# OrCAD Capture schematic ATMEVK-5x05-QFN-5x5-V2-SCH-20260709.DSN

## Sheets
1 01. TITLE: title: ATM5305/5205 5x5 QFN EVALUATION BOARD; rev: 2; note: 108-20-210-xxxx
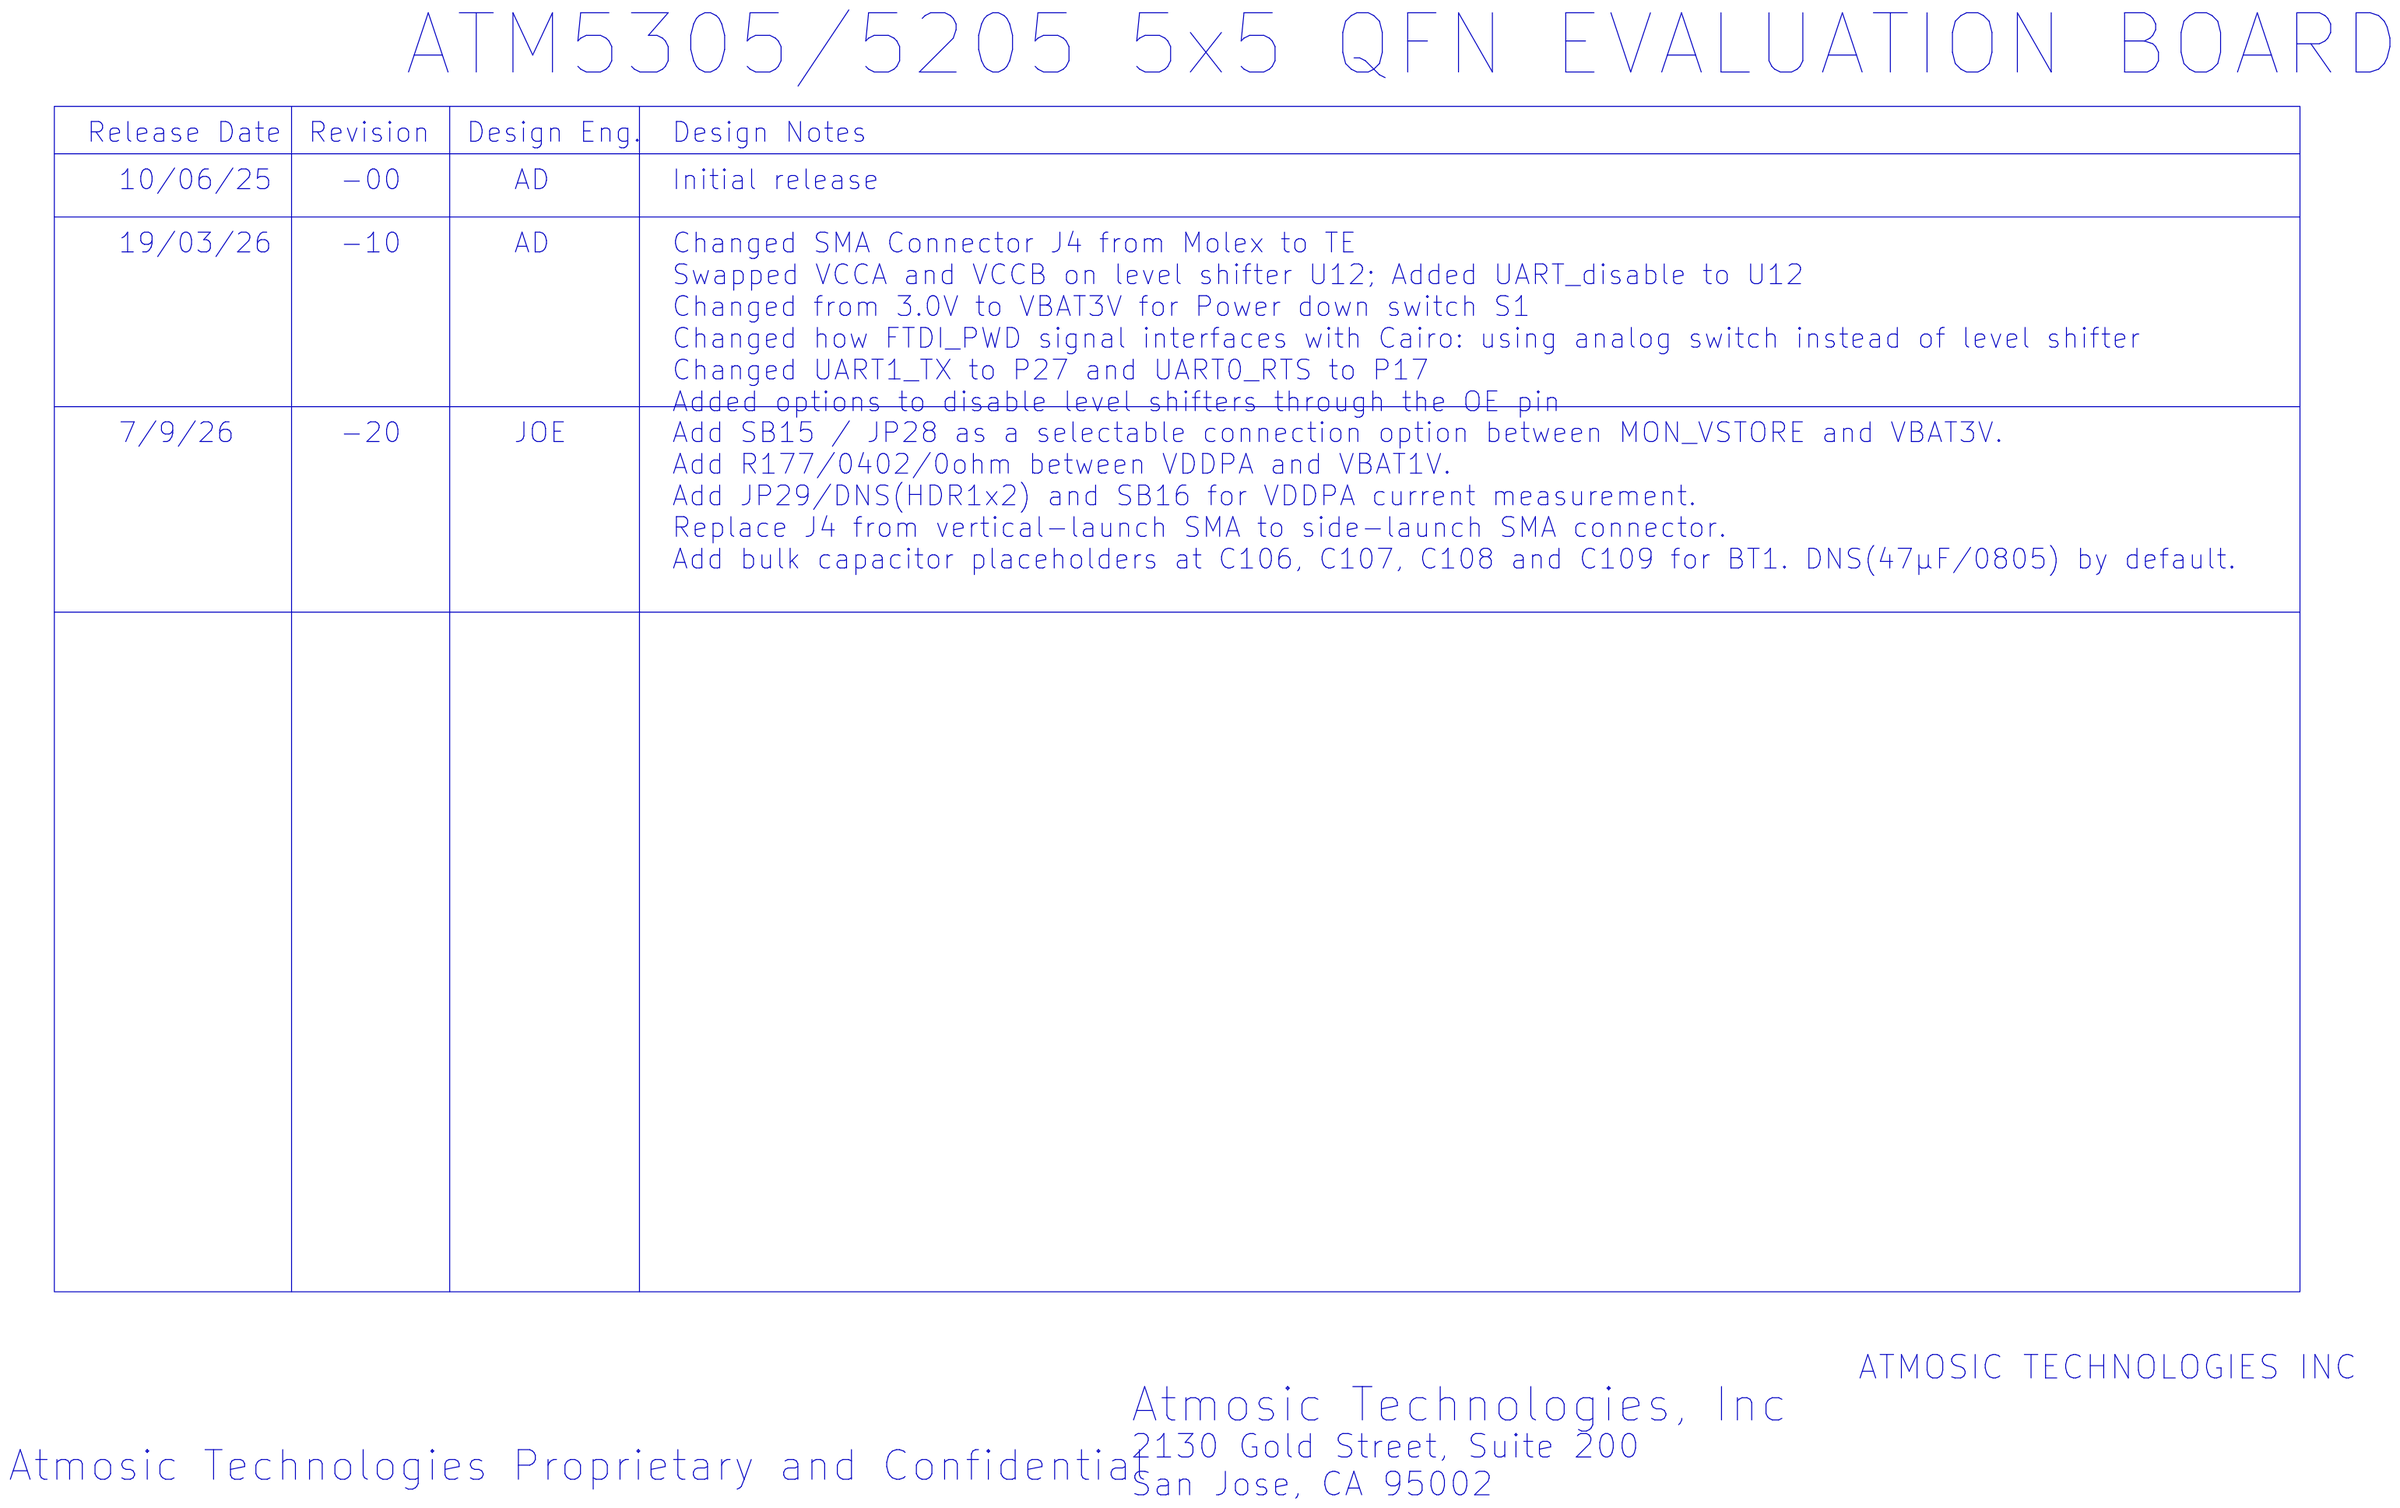
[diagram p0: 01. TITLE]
2 02. Block Diagram: title: ATM5305 QFN 5x5 EVALUATION BOARD
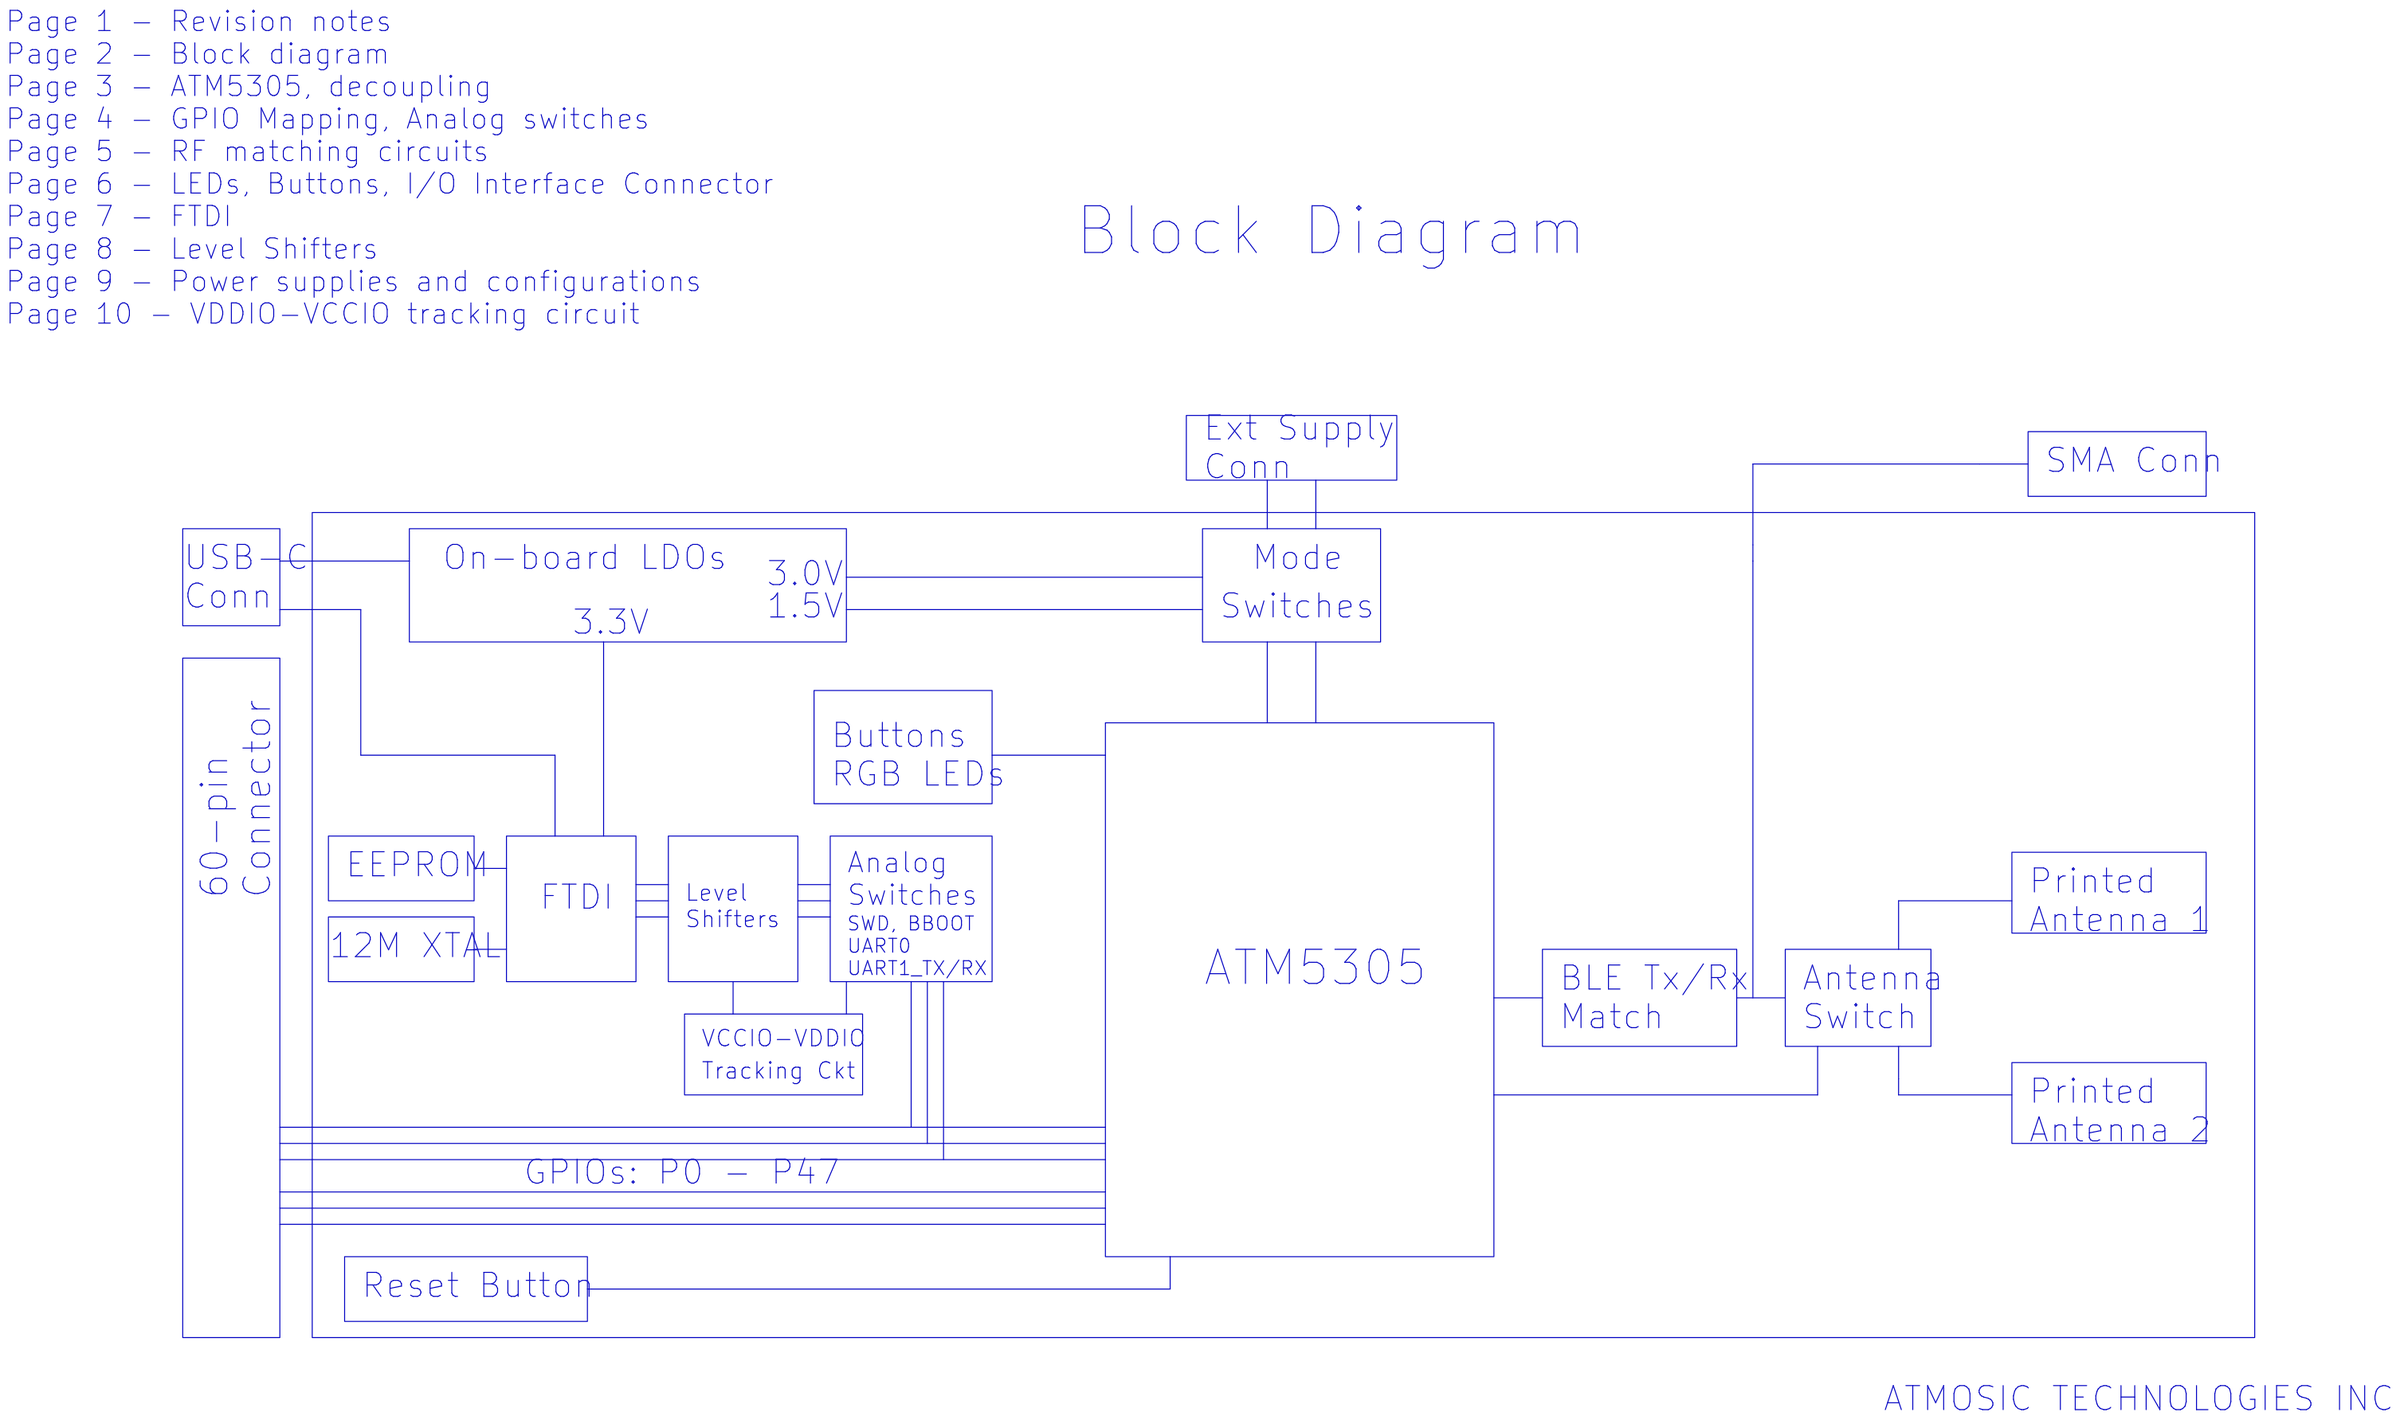
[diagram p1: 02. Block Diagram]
3 03. ATM5305-2NC8QK: size B; title: ATM5305 QFN 5x5 EVALUATION BOARD
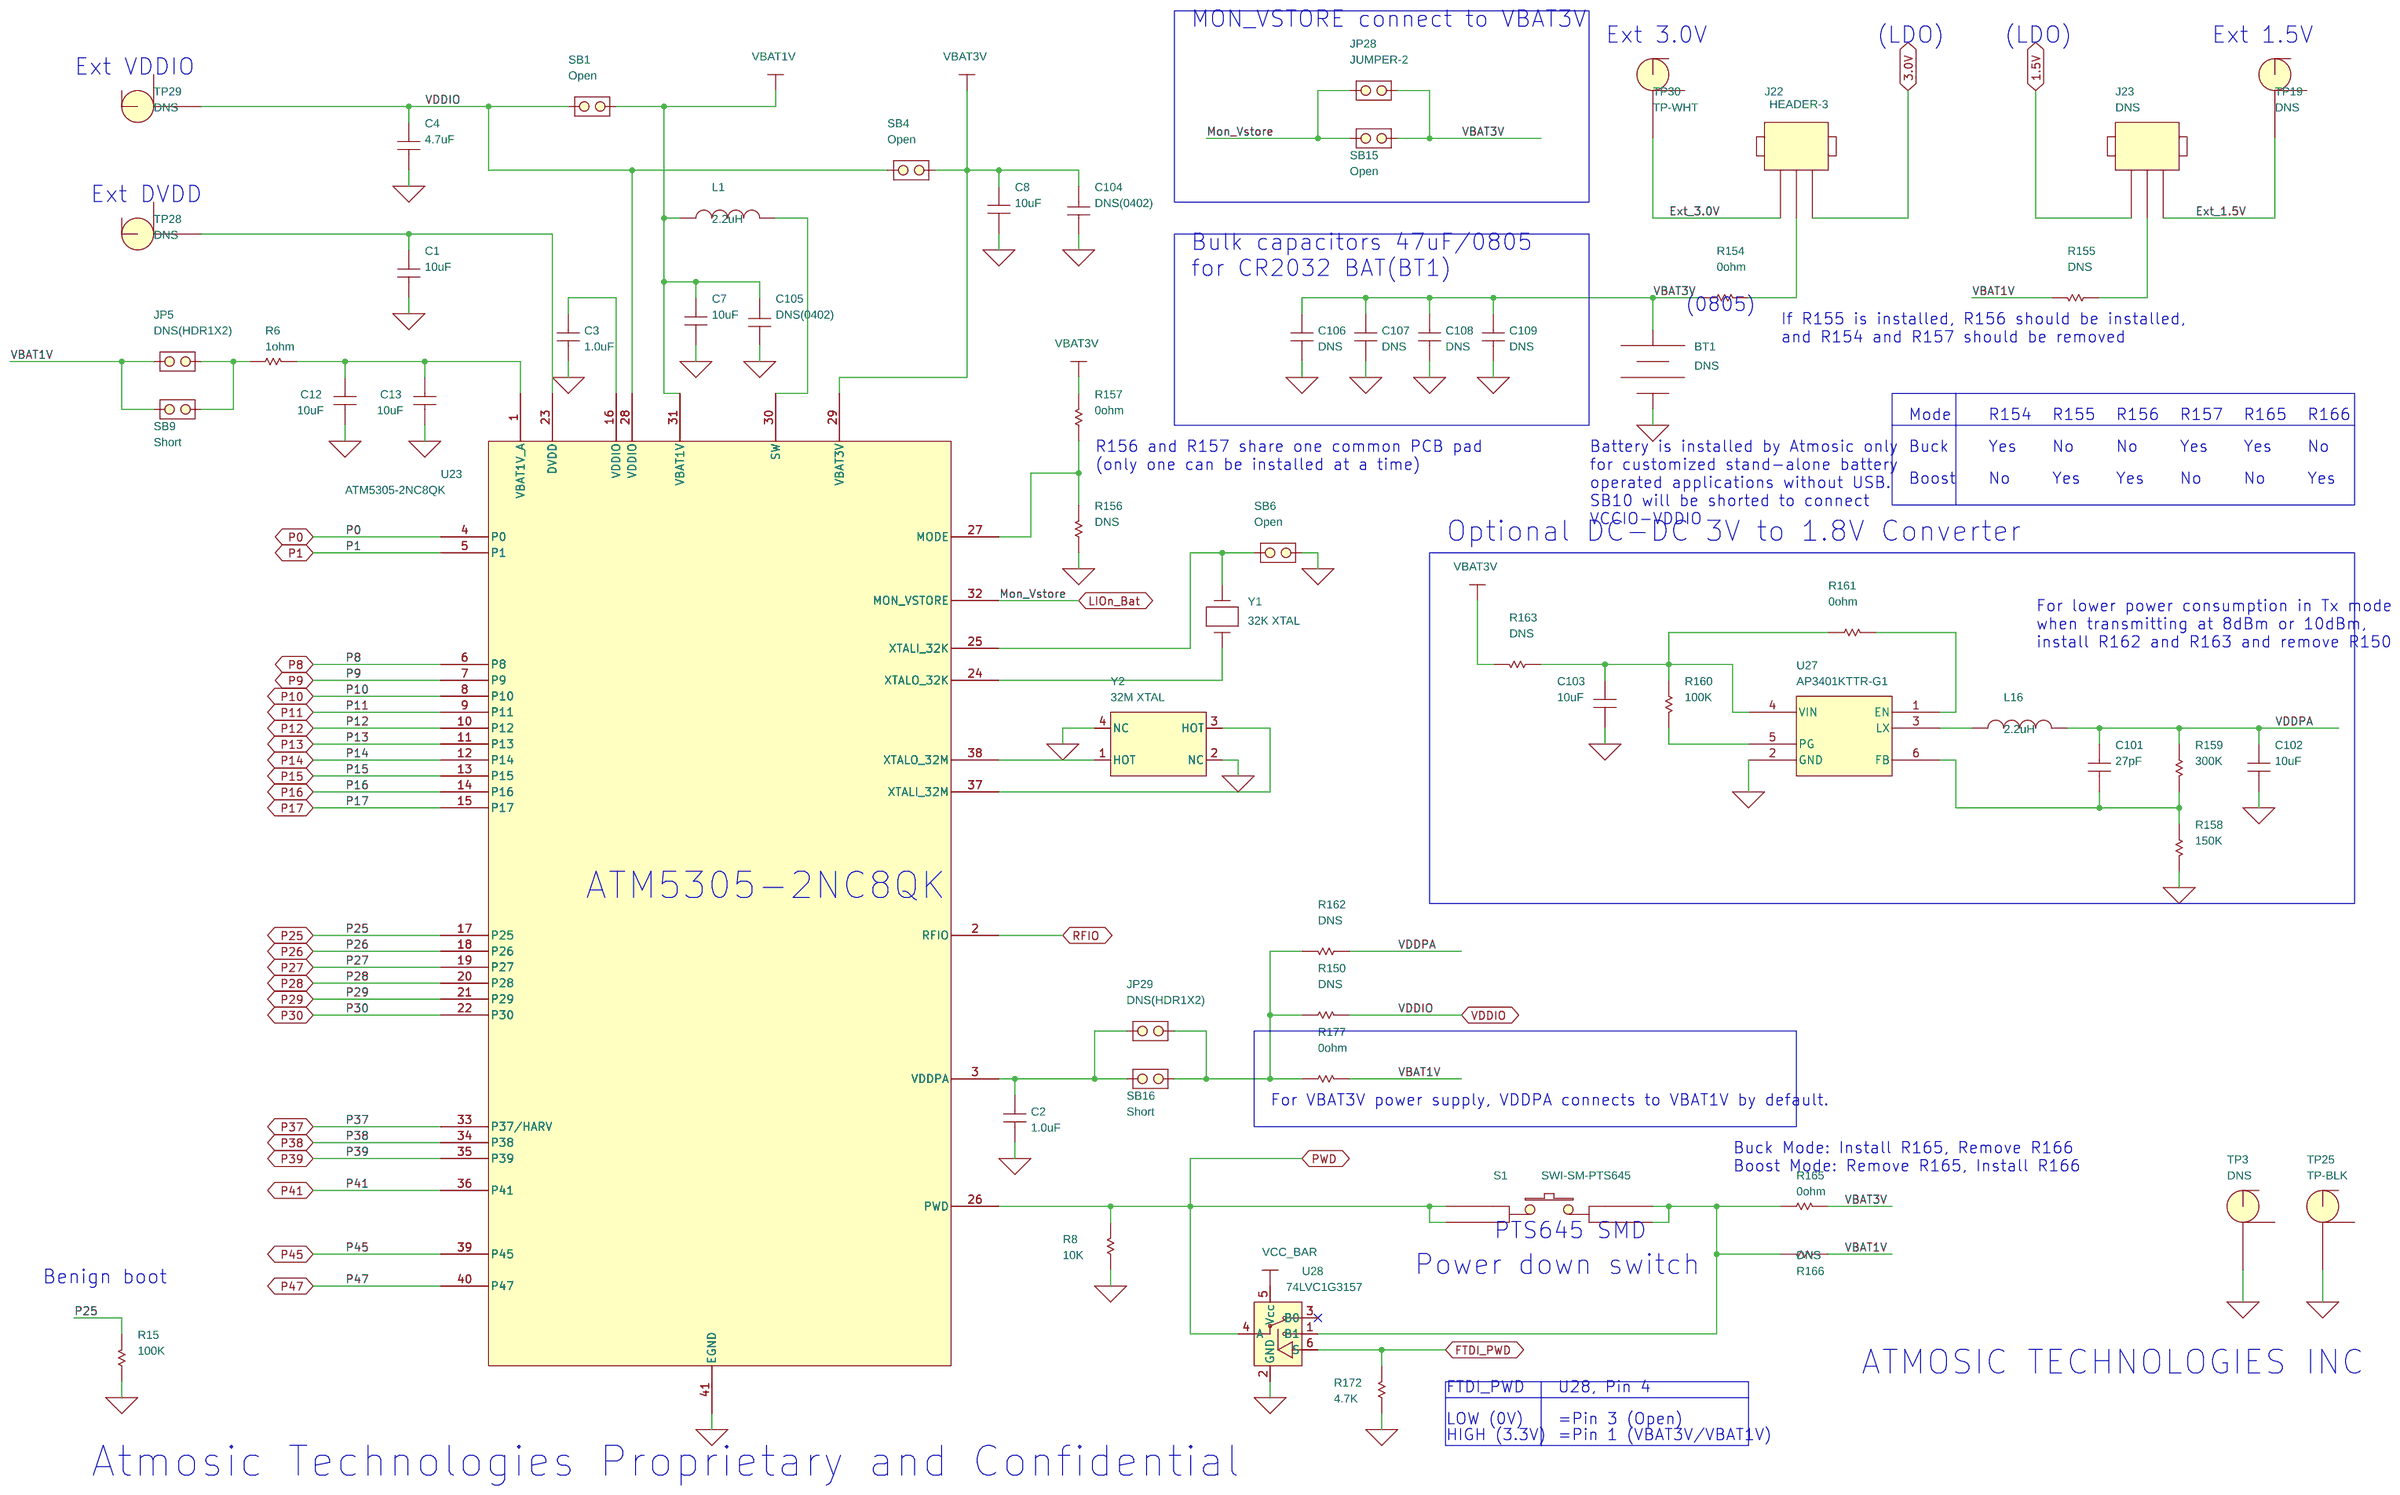
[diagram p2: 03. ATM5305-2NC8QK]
4 04. GPIO Mapping: size B; title: ATM5305 QFN 5x5 EVALUATION BOARD
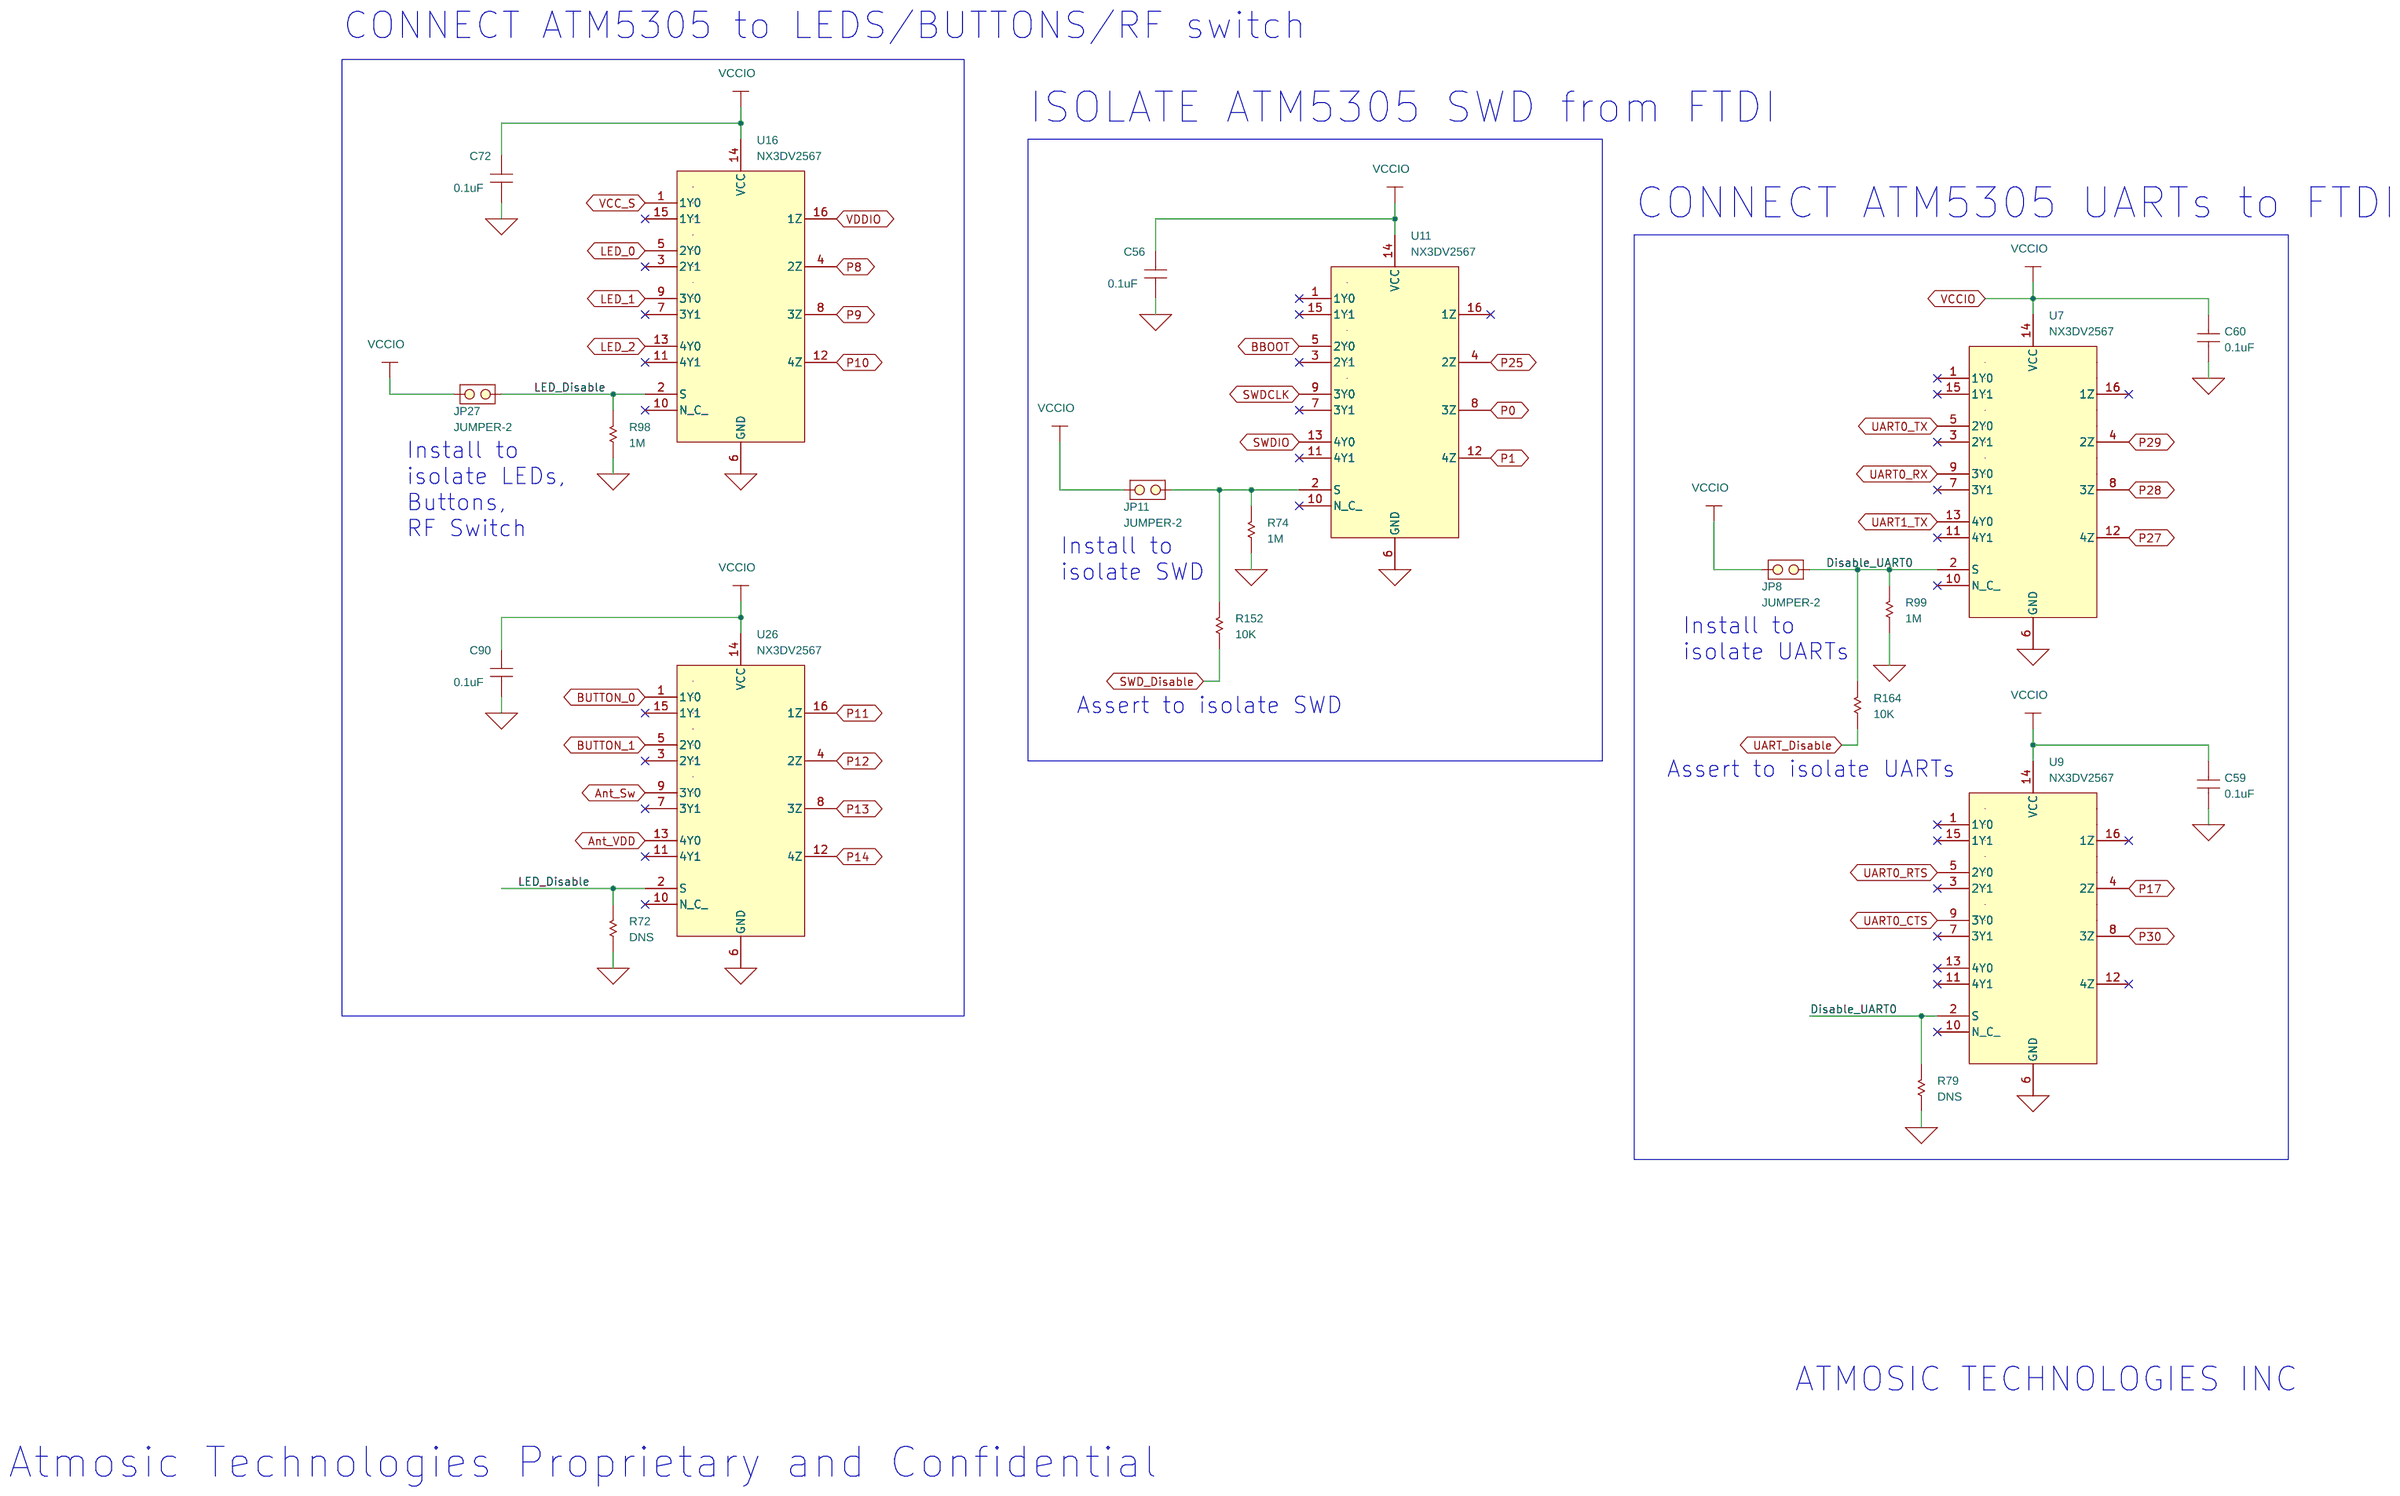
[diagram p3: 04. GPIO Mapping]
5 07. FTDI and USB: size B; title: ATM5305 QFN 5x5 EVALUATION BOARD
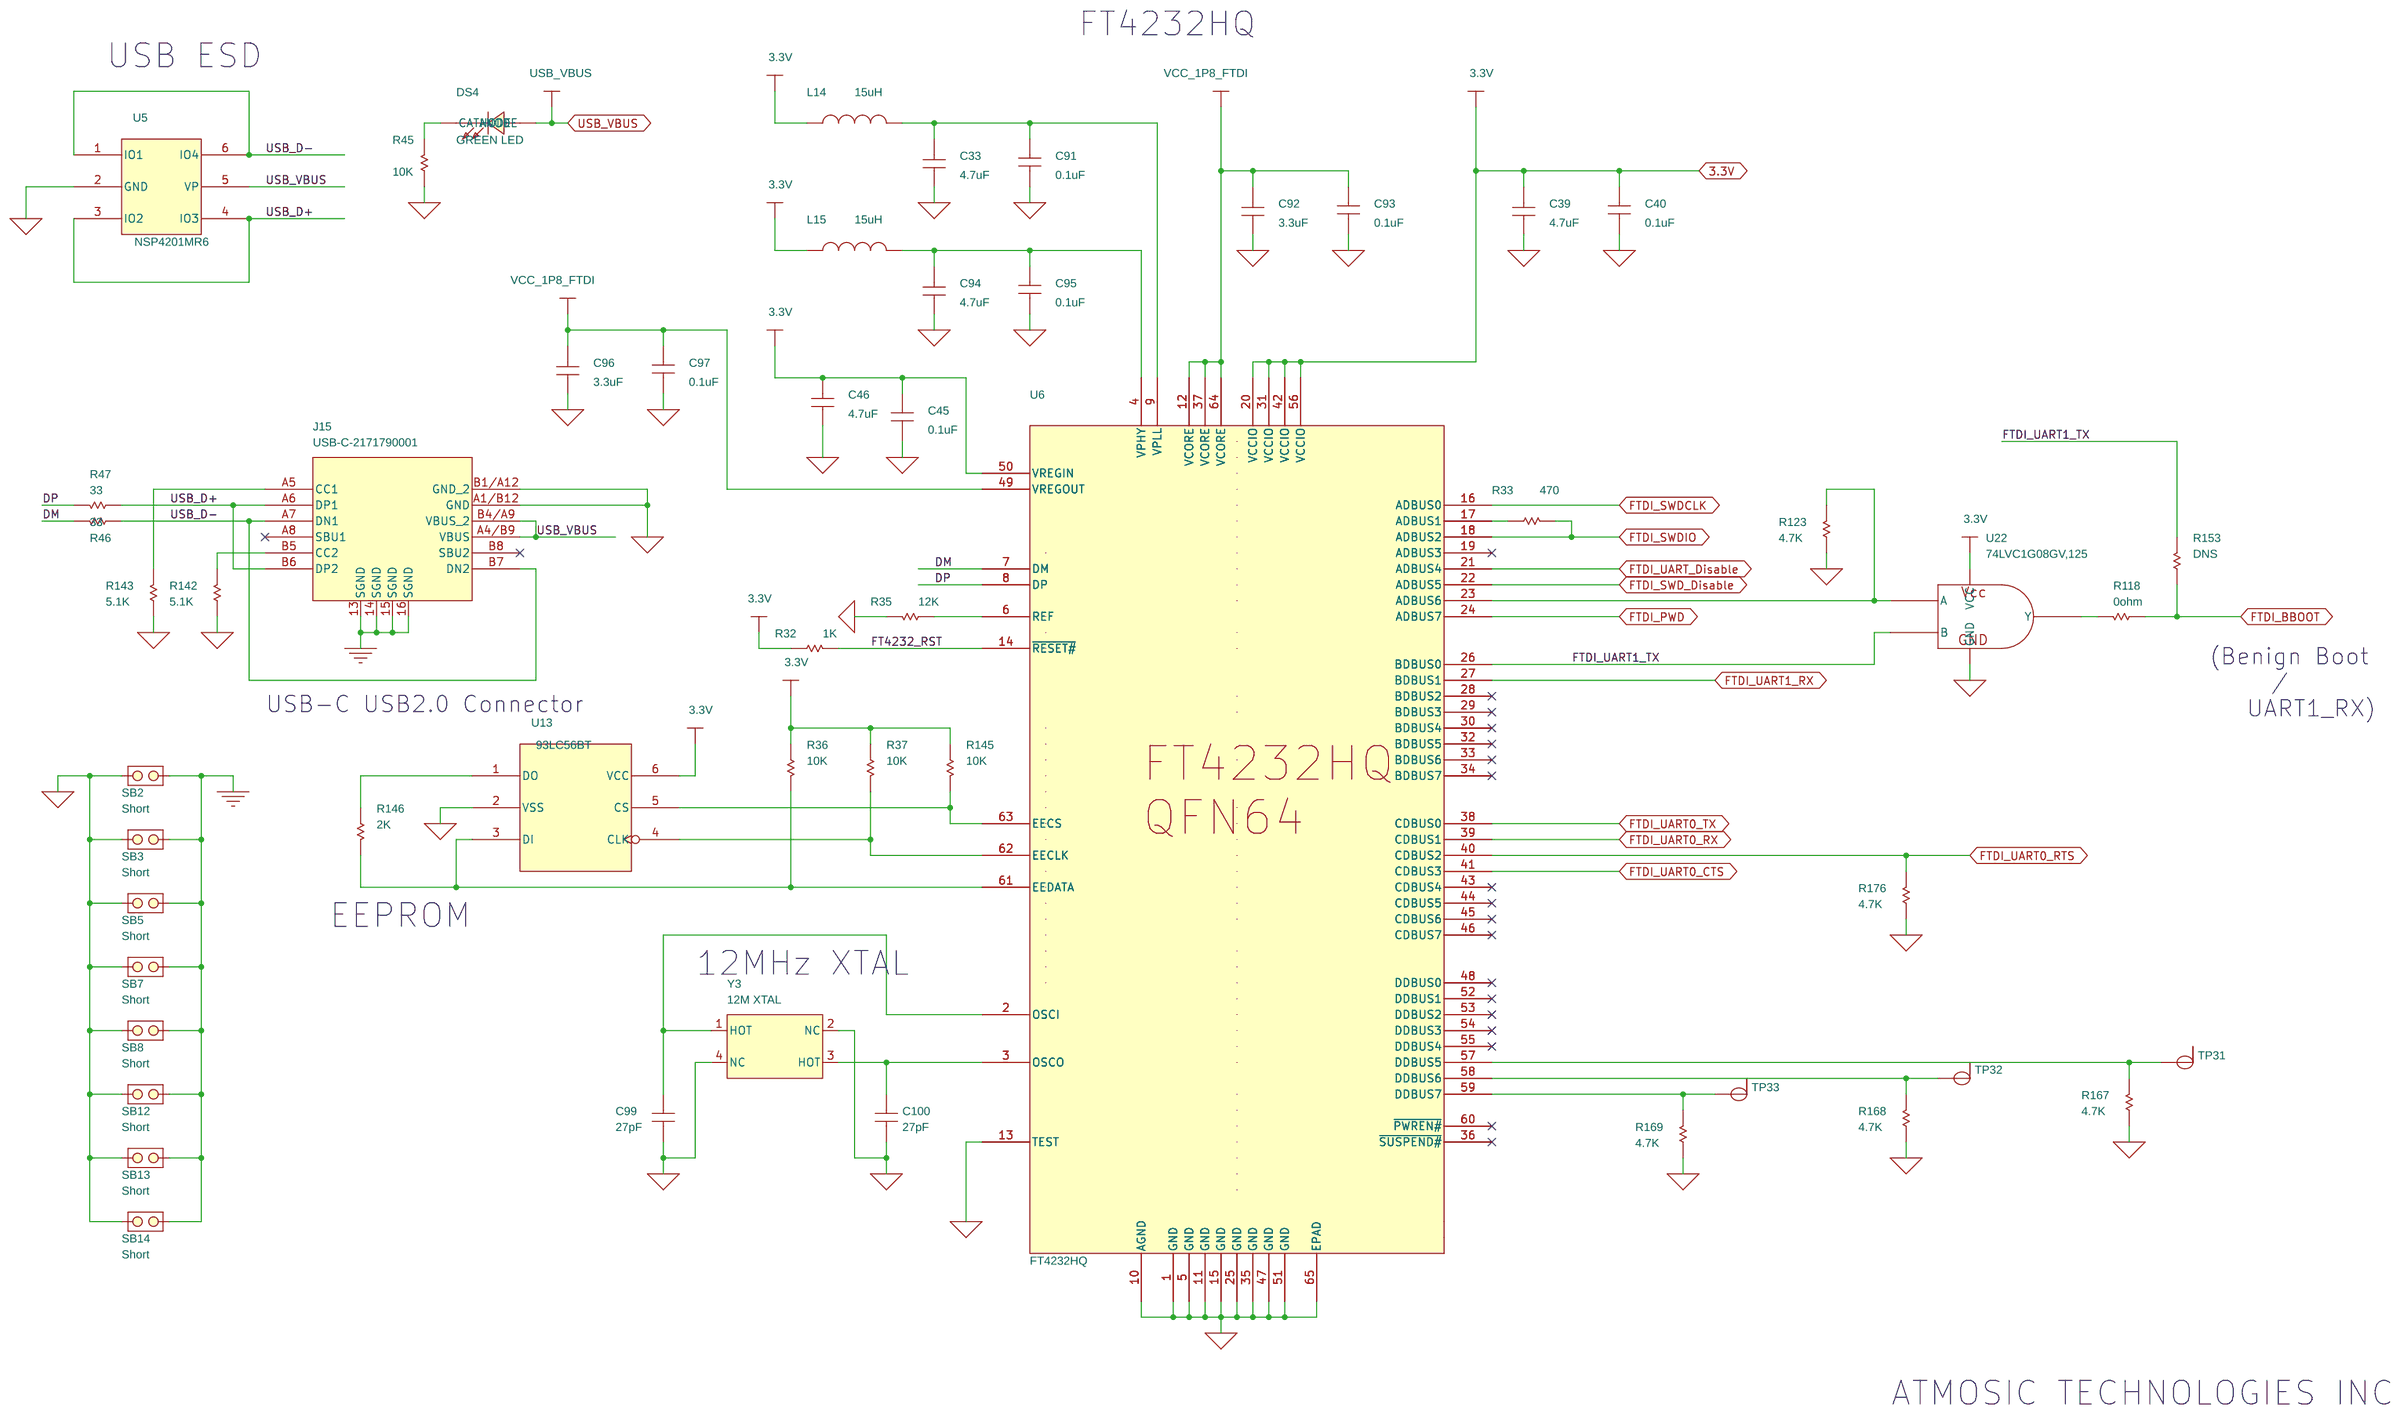
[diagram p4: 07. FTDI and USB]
6 08. Level Shifters: size B; title: ATM5305 QFN 5x5 EVALUATION BOARD
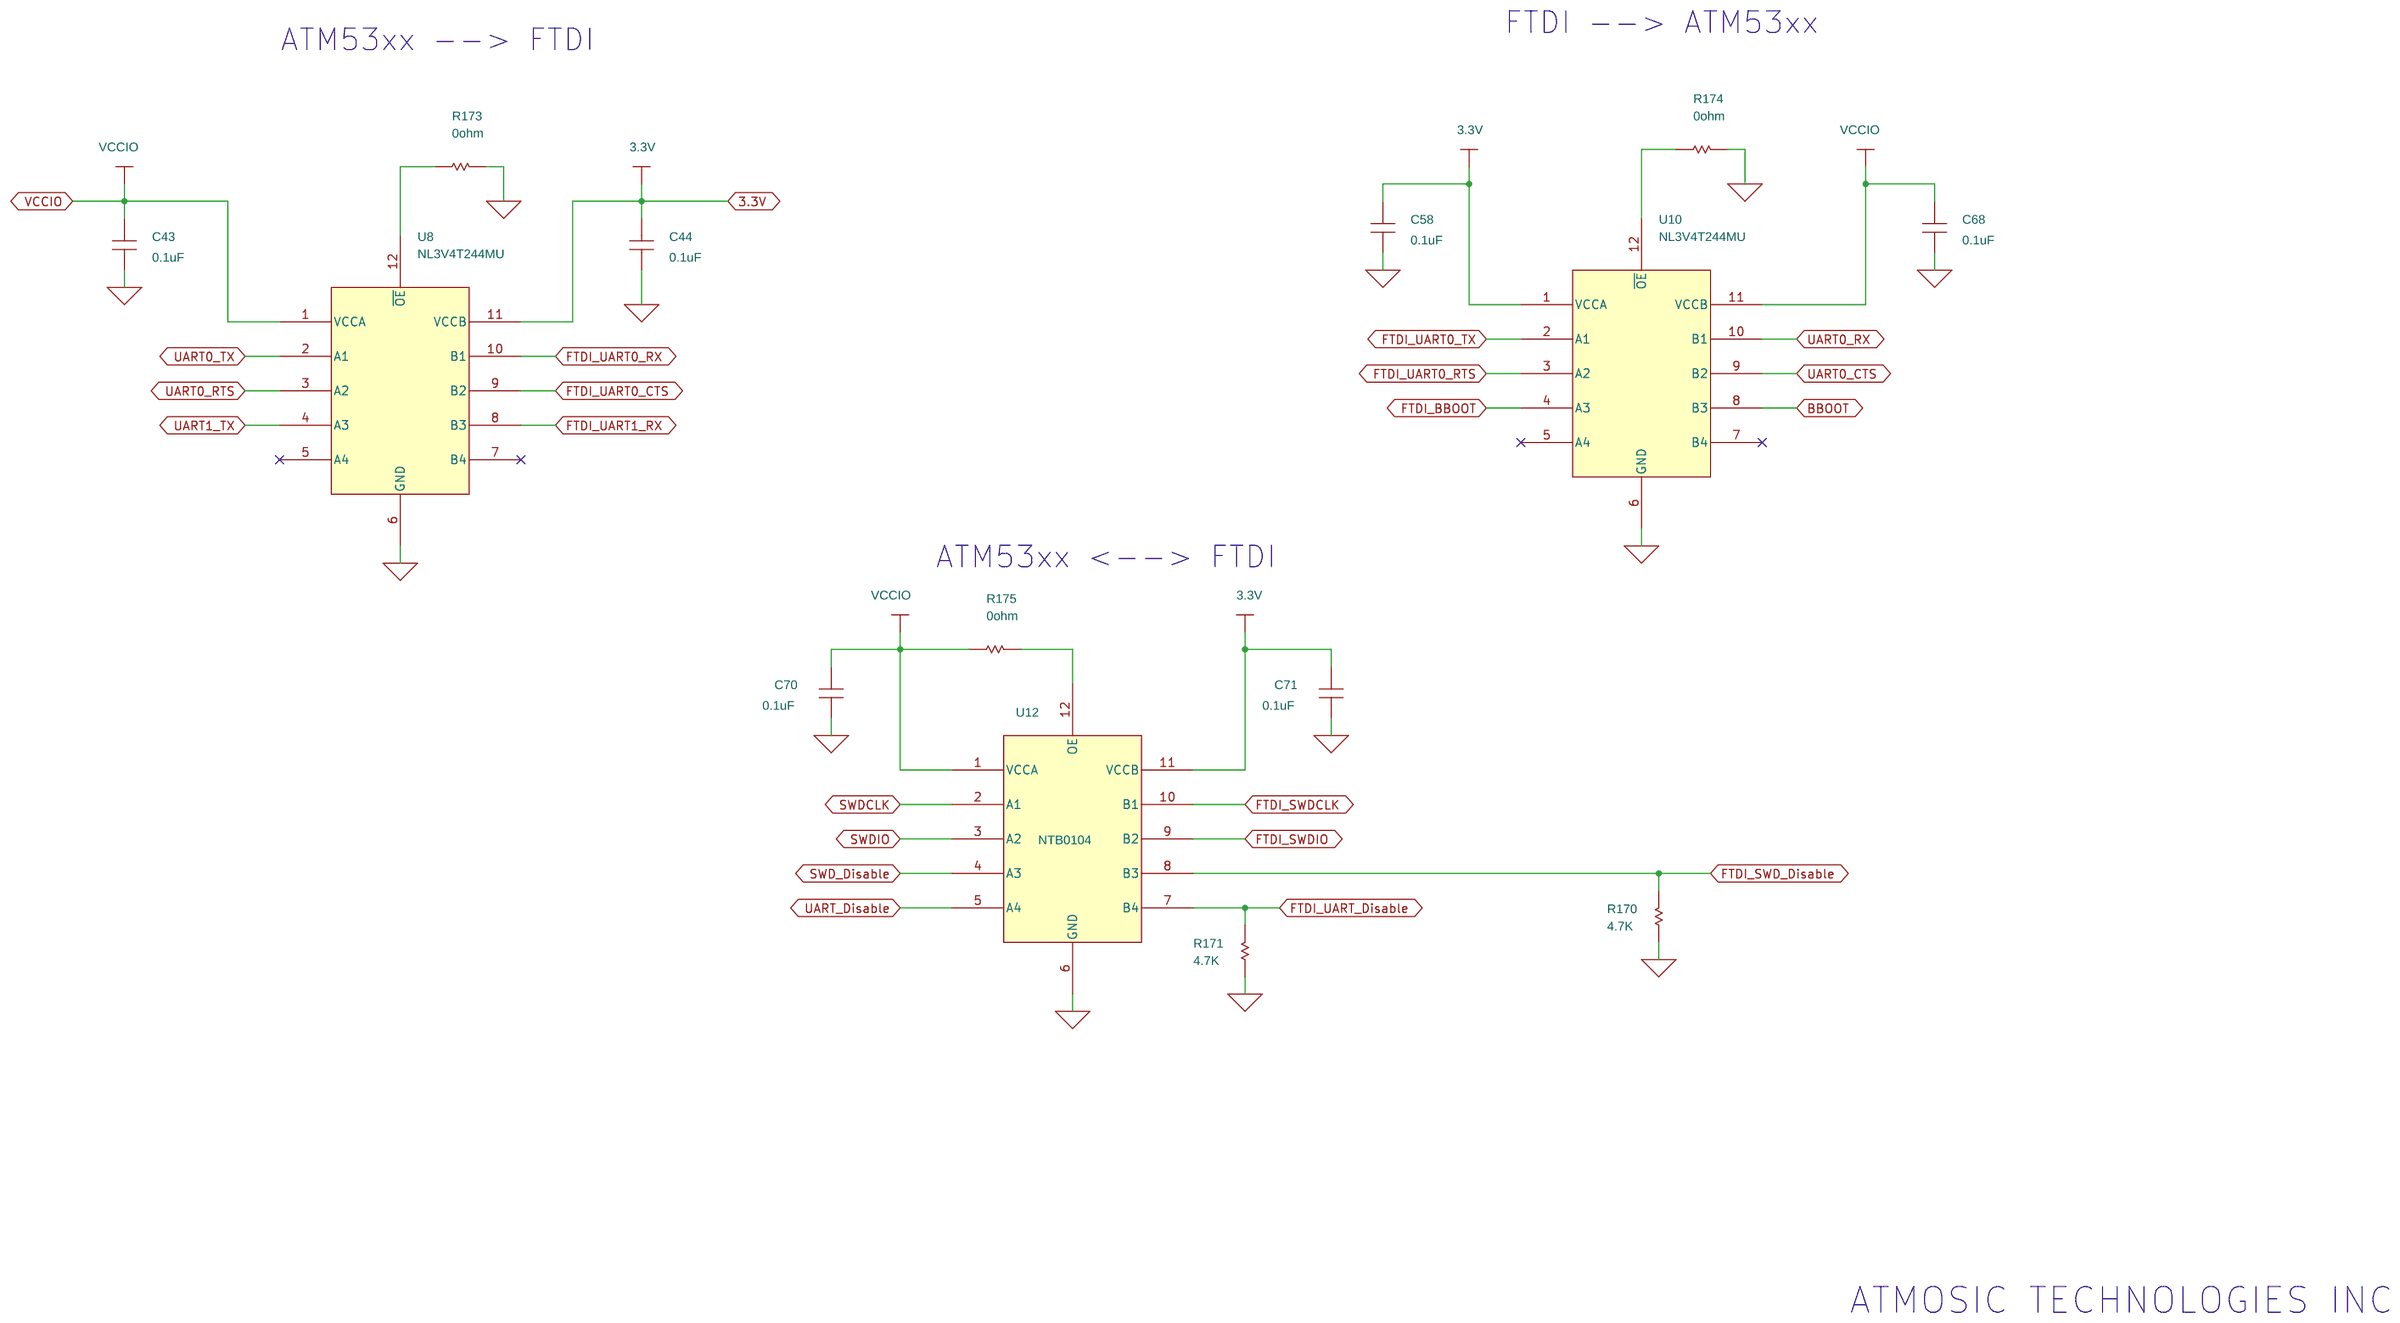
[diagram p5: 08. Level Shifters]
7 09. Power: size B; title: ATM5305 QFN 5x5 EVALUATION BOARD
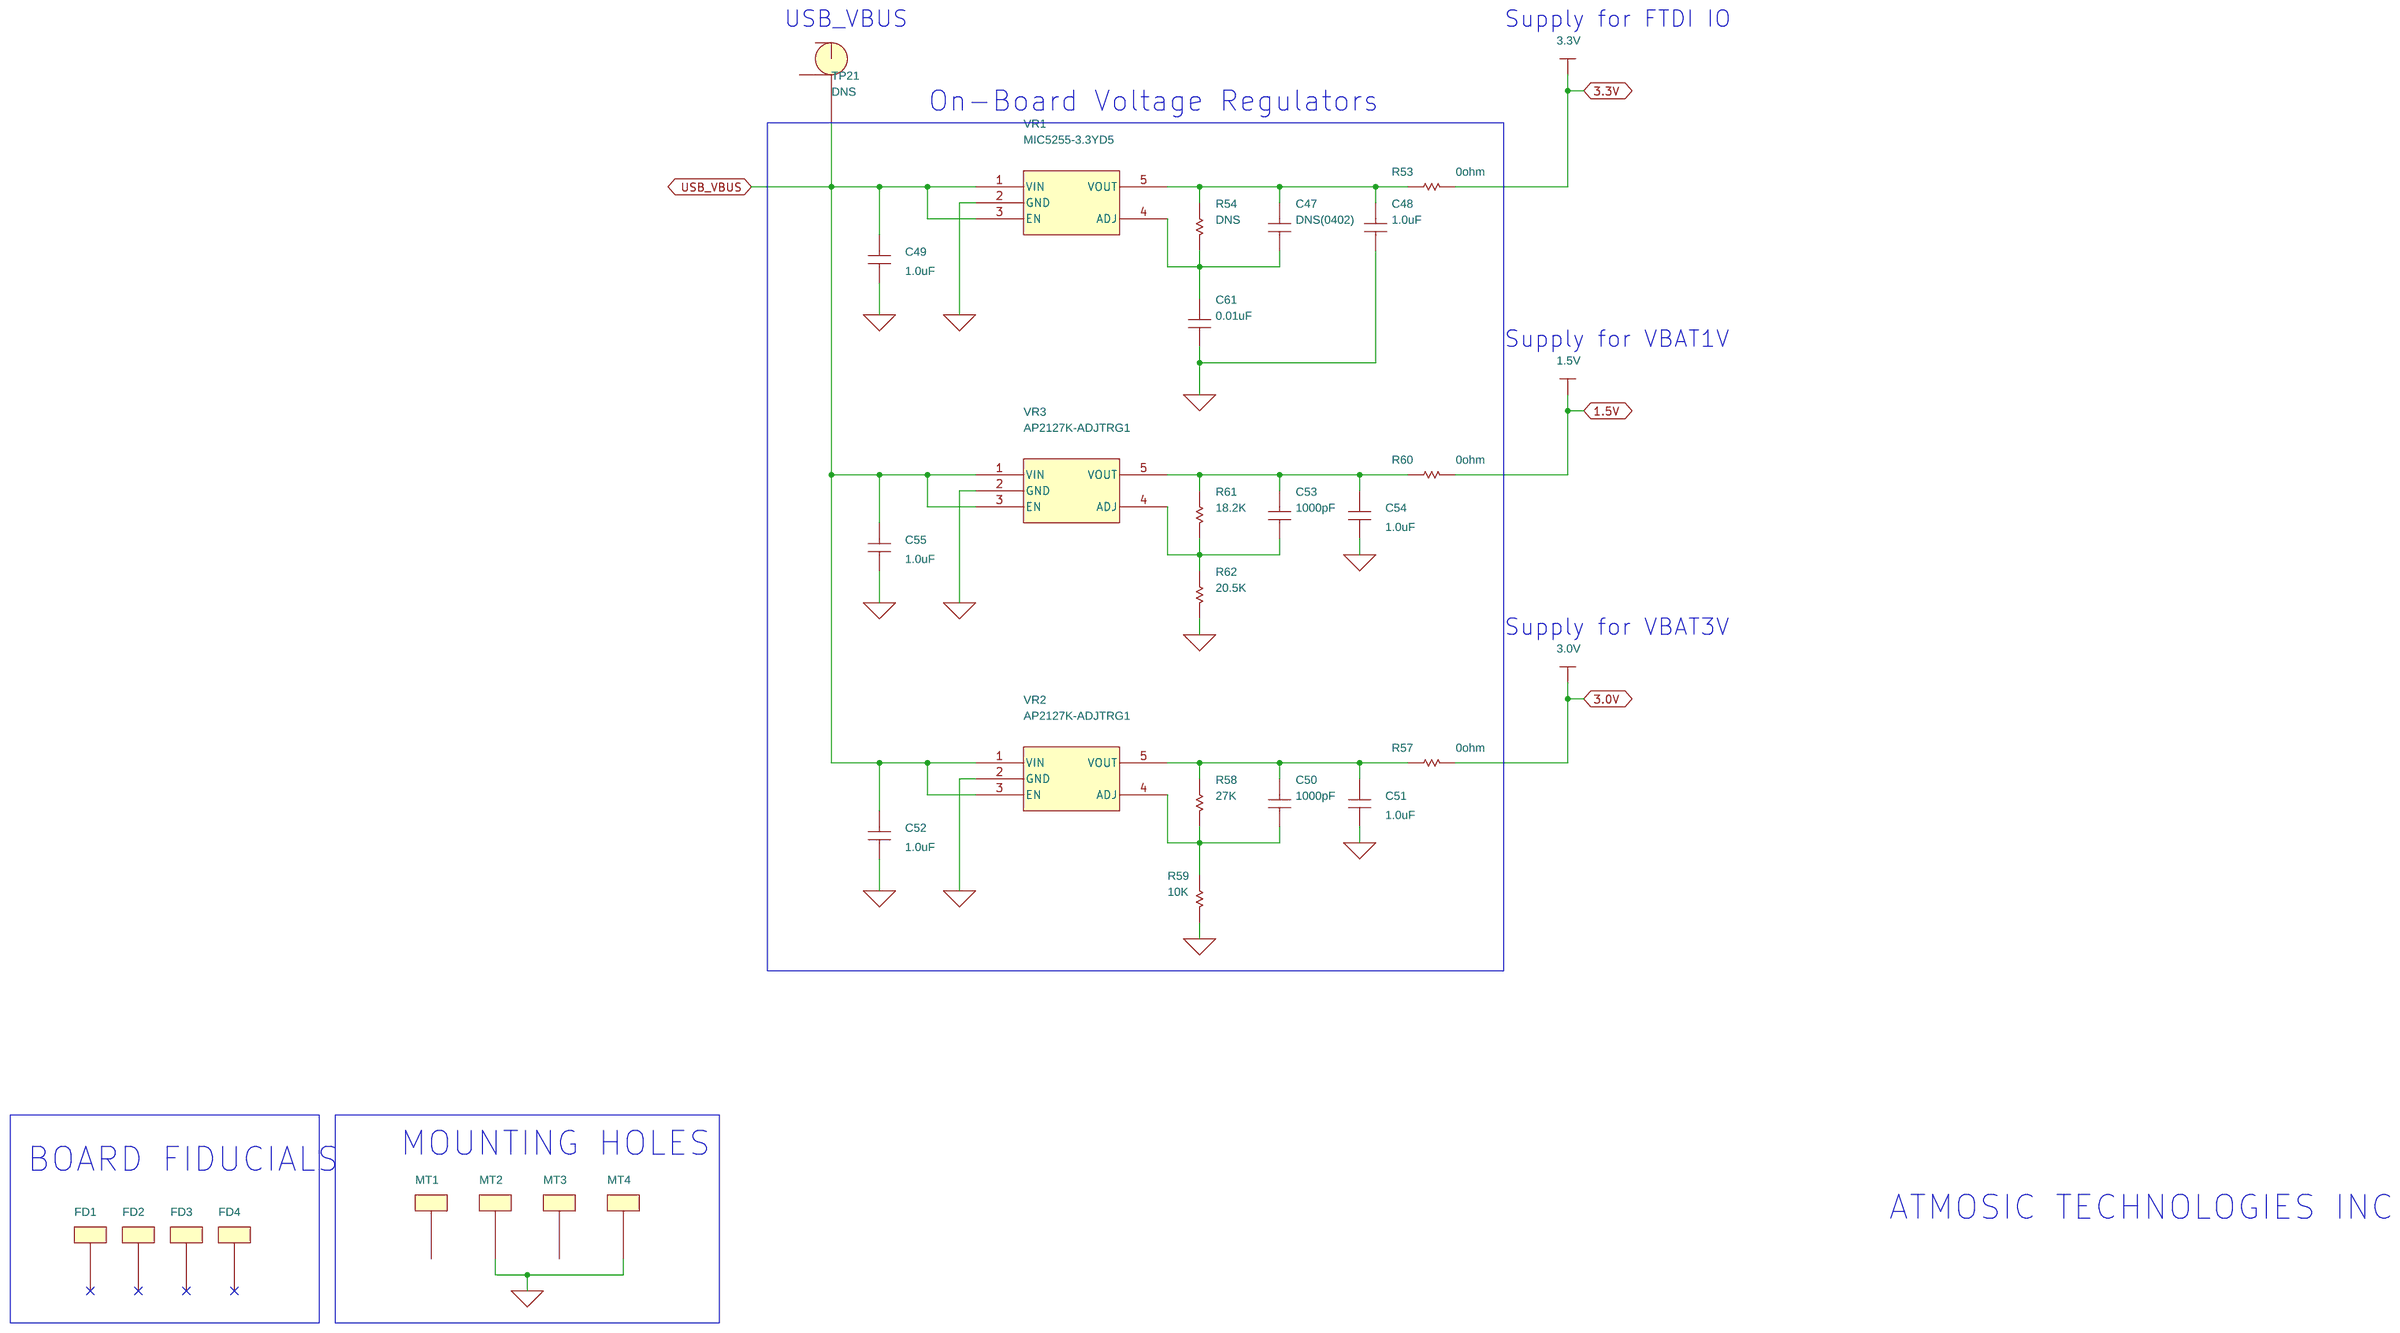
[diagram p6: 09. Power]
8 10. VDDIO-VCCIO Tracking: size B; title: ATM5305 QFN 5x5 EVALUATION BOARD
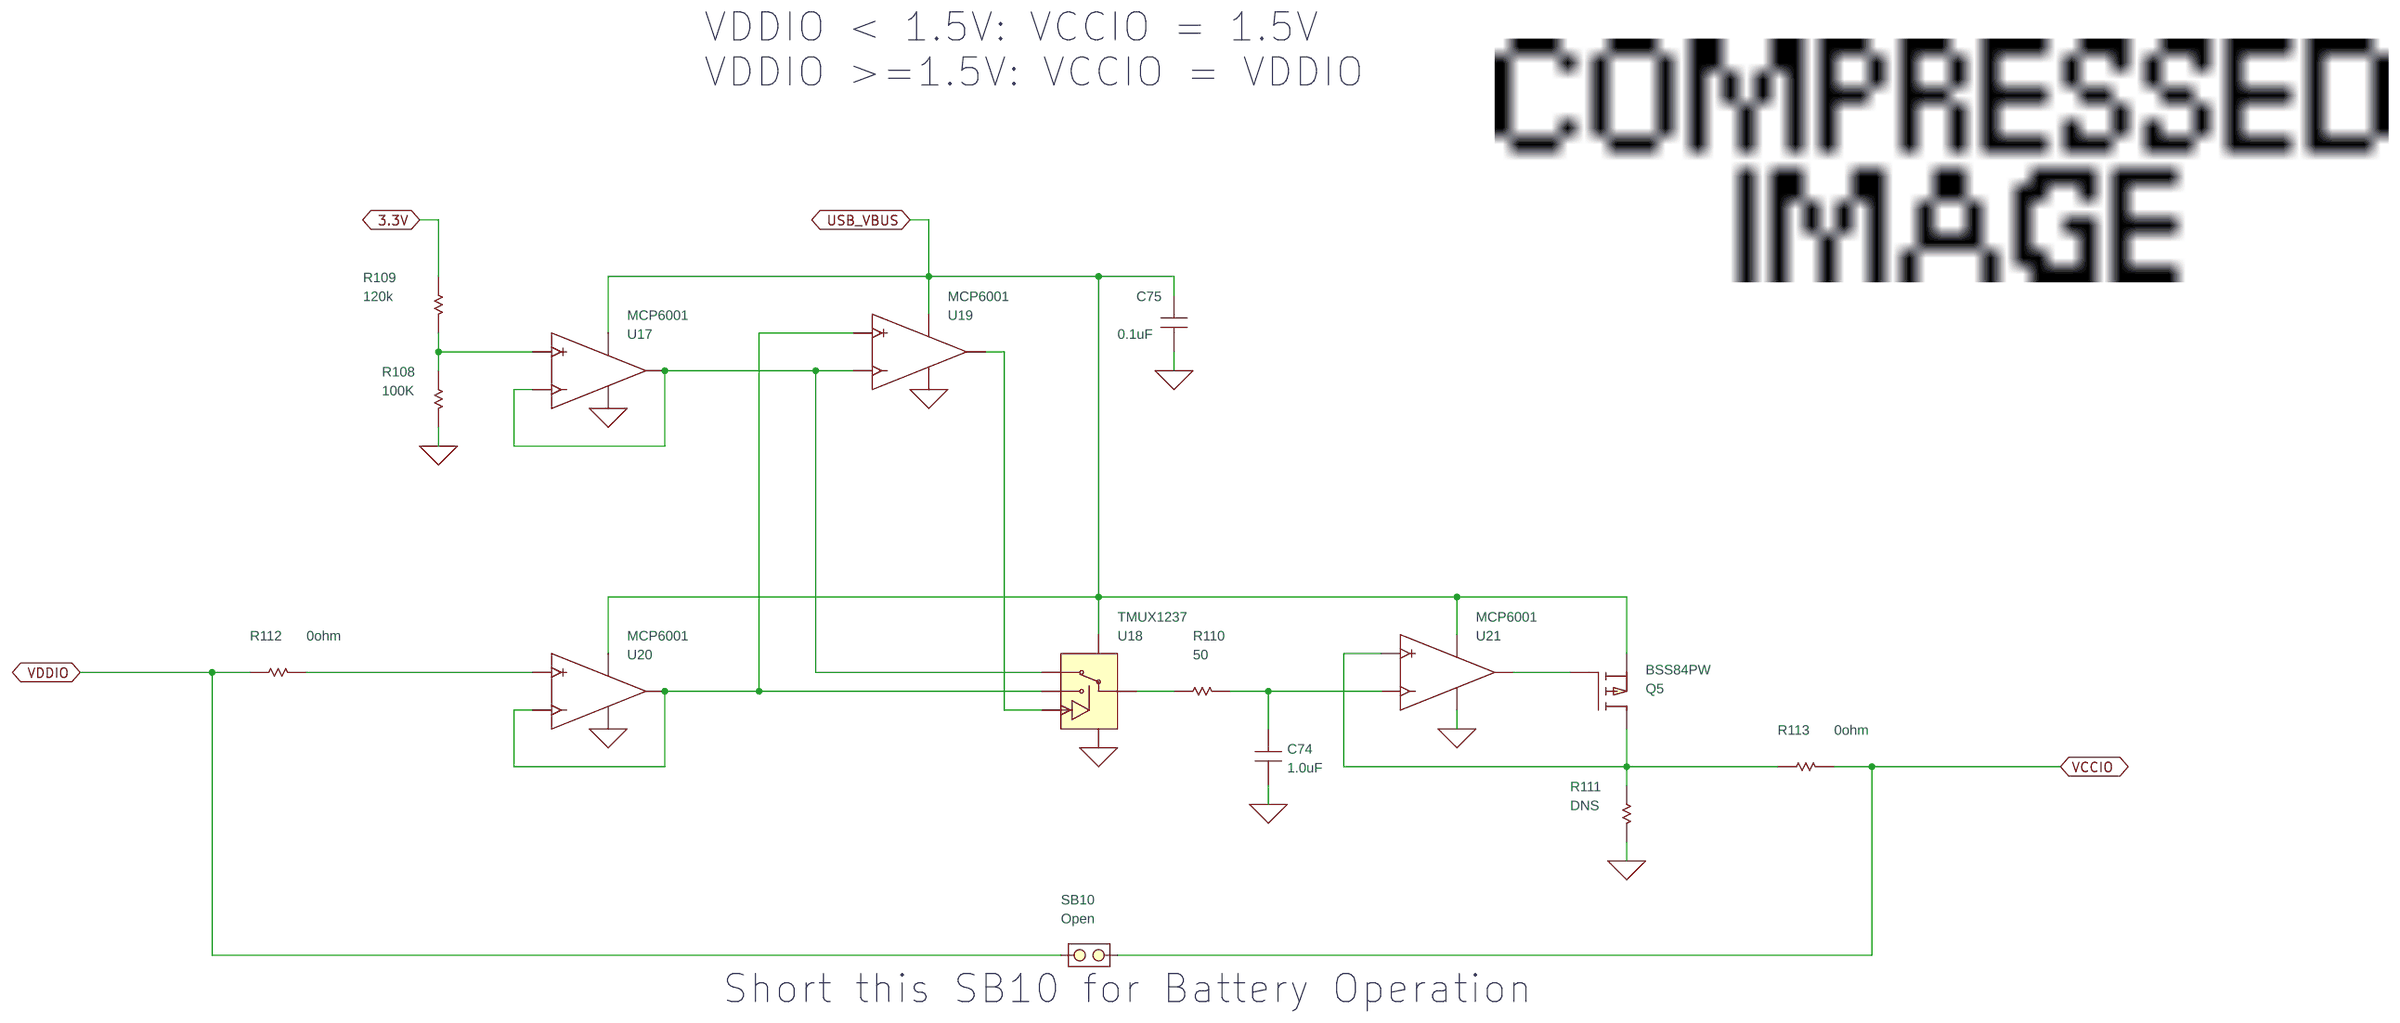
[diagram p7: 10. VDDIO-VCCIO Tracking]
9 06. Buttons, LEDs, I/O: size B; title: ATM5305 QFN 5x5 EVALUATION BOARD
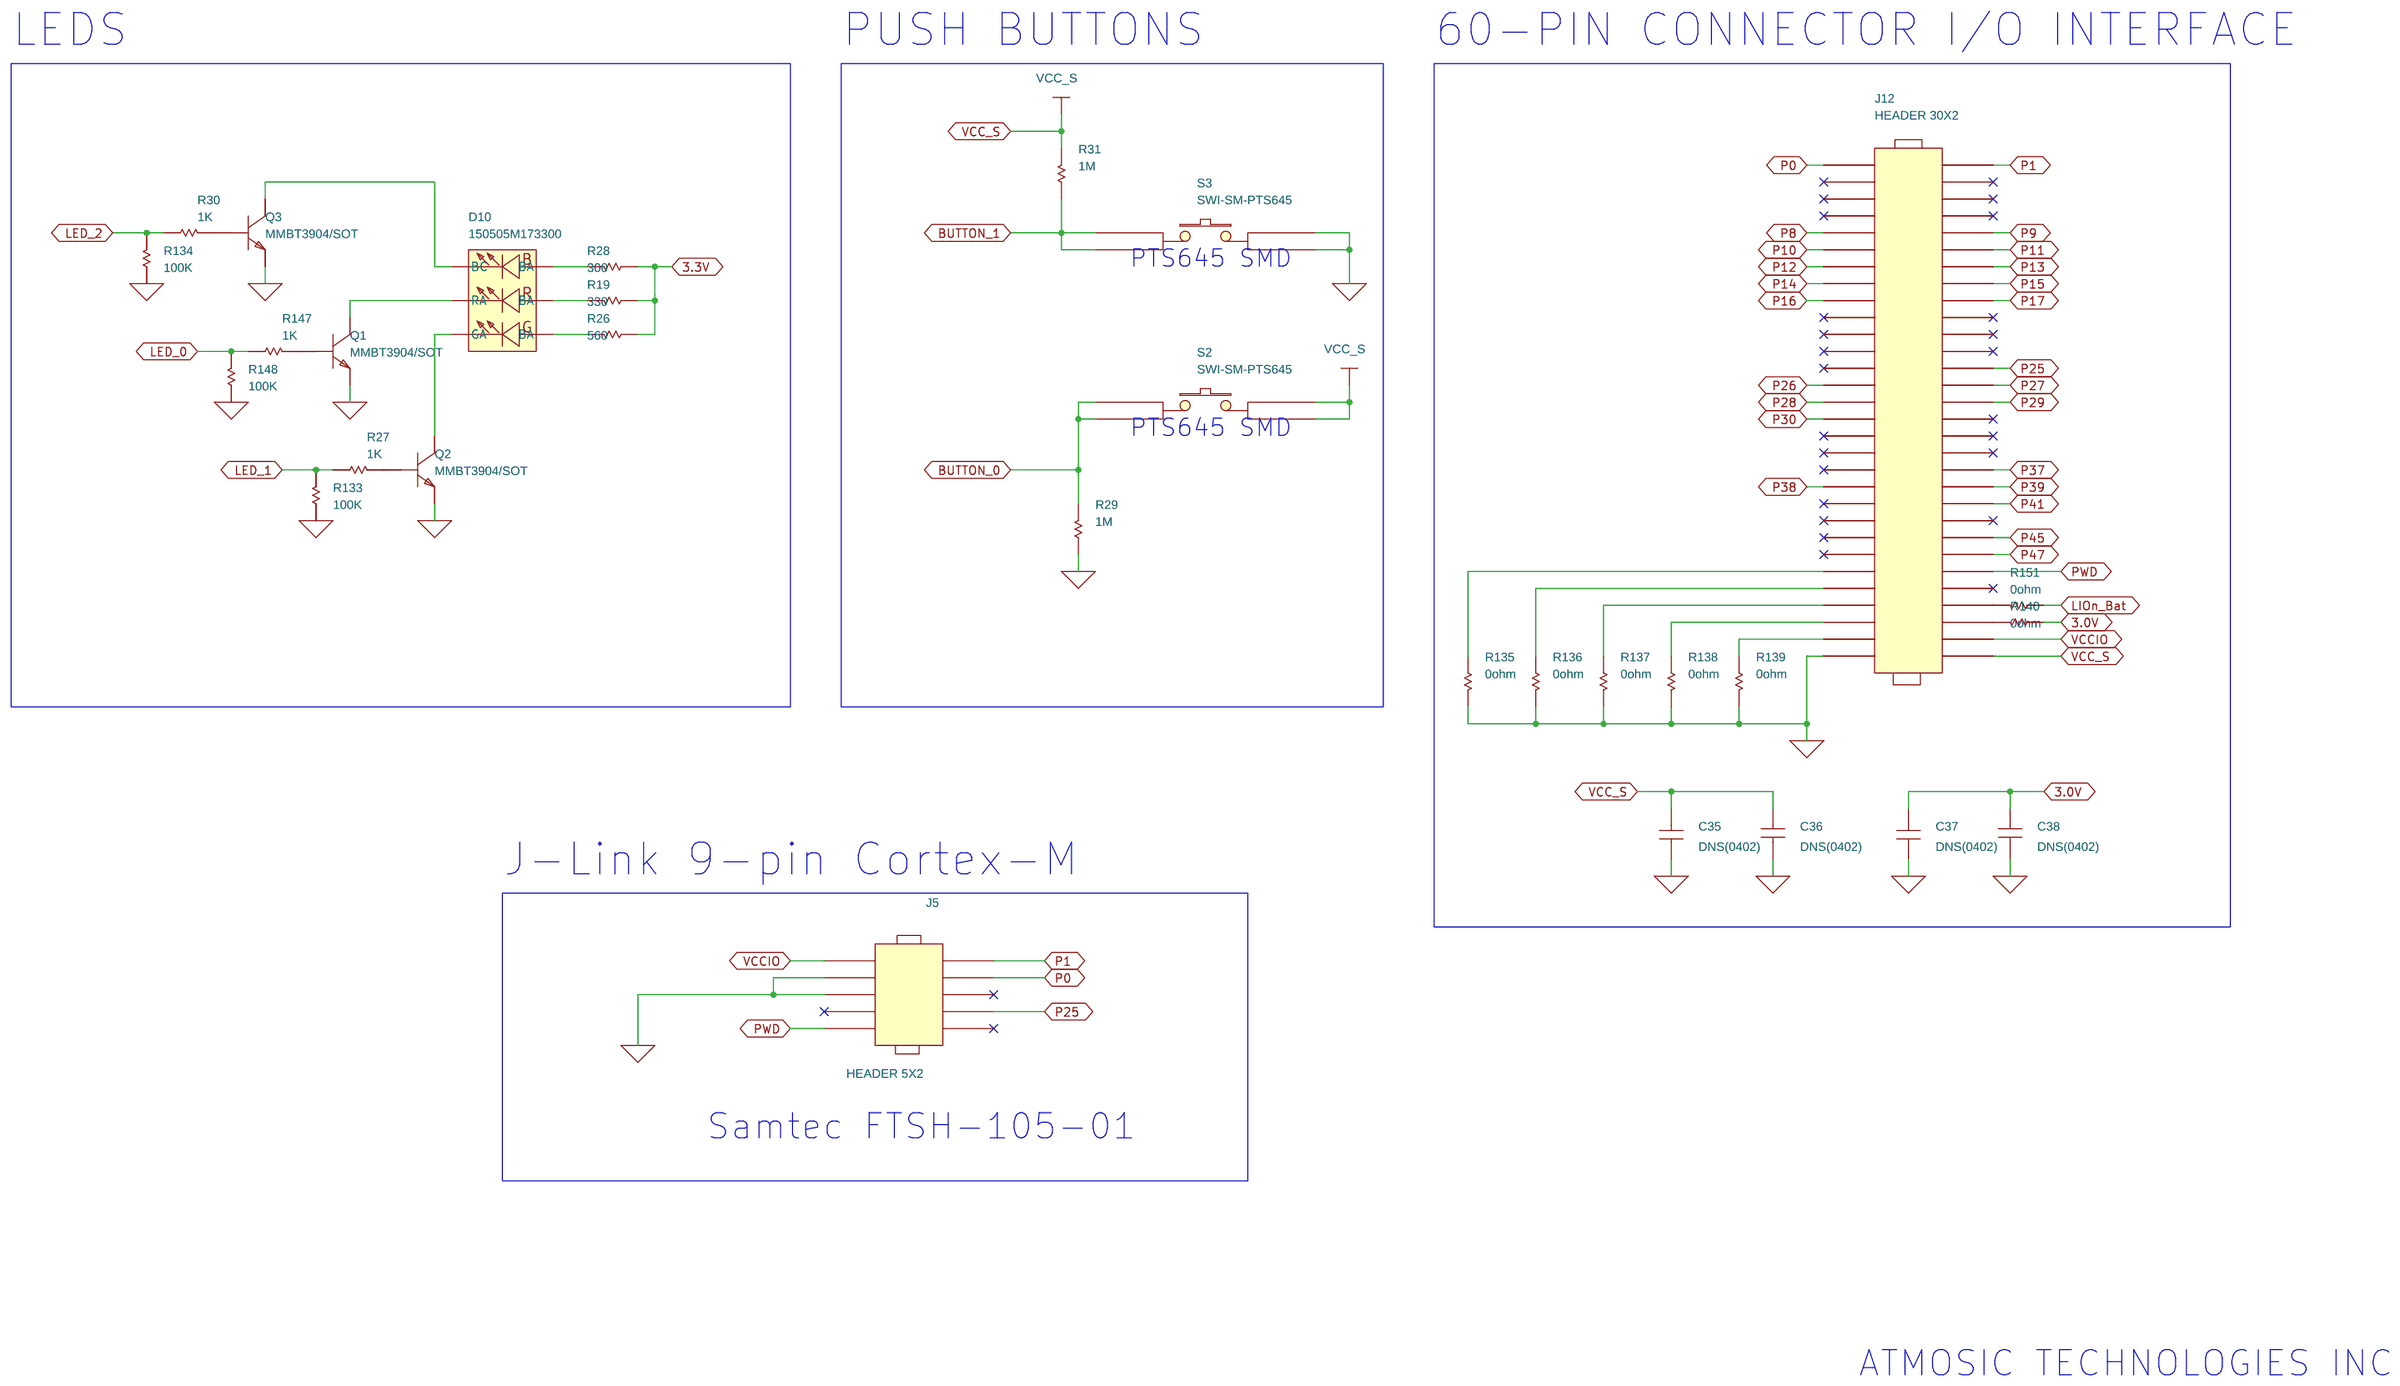
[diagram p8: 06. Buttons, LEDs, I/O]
10 05. RF (RFIO/Switch/Antenna): size B; title: ATM5305 QFN 5x5 EVALUATION BOARD
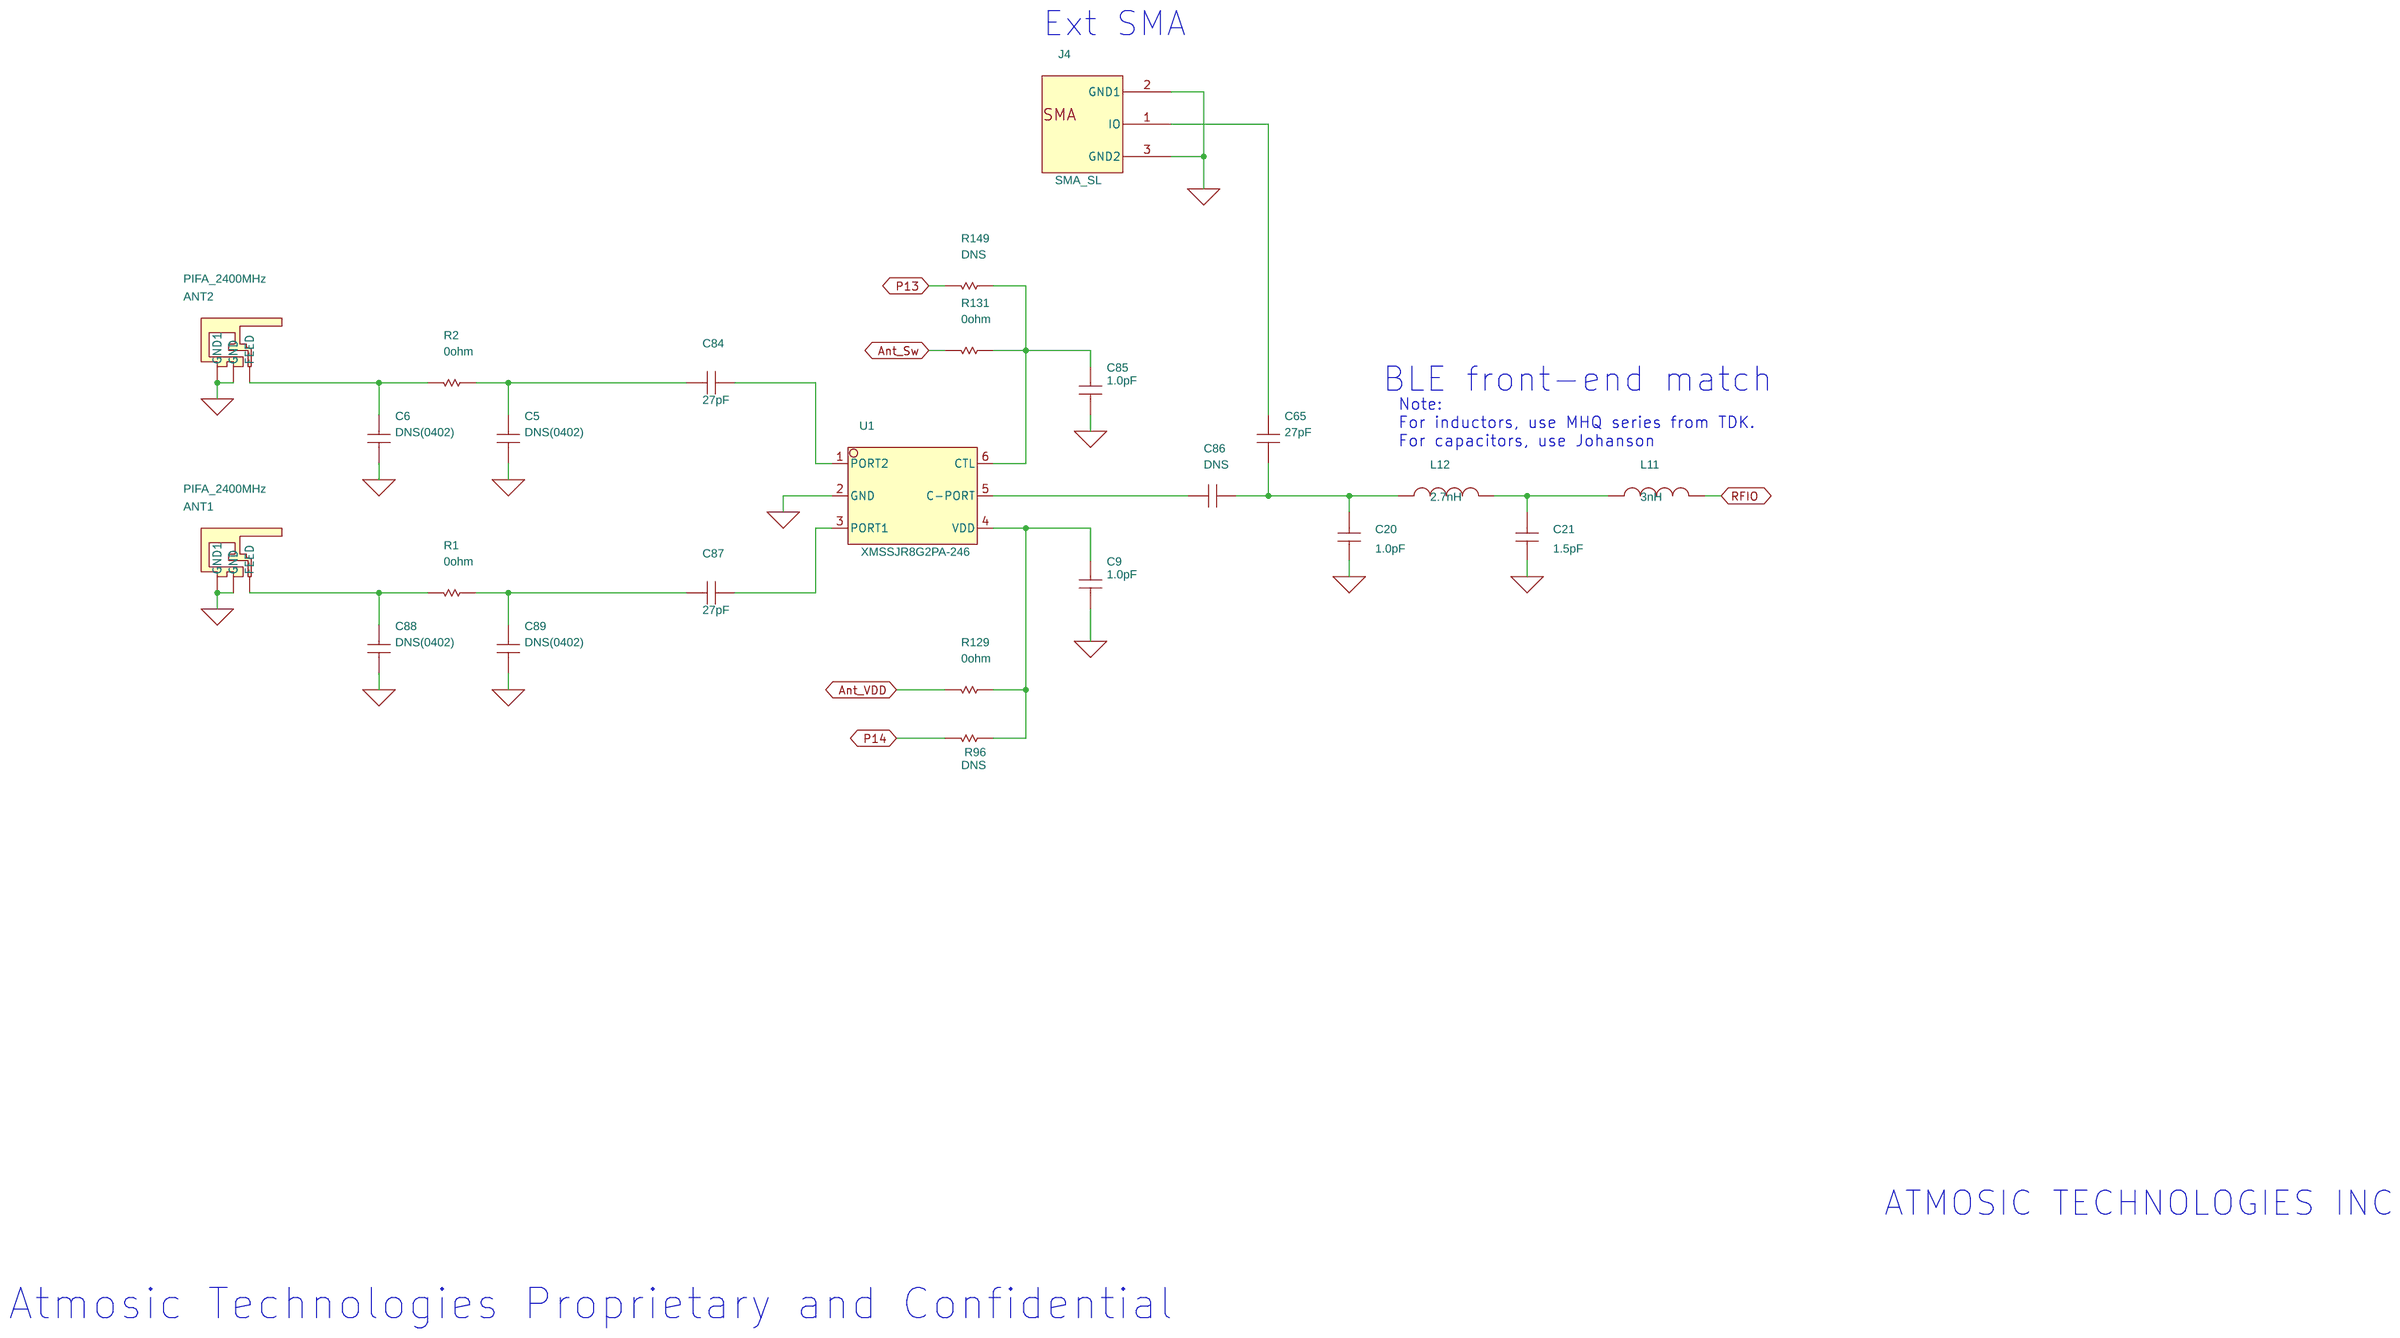
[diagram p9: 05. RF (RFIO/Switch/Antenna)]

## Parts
sheet 03. ATM5305-2NC8QK
BT1  DNS  [BAT-HOLDER-2032]
C1  10uF  [0402]
C2  1.0uF  [0402]
C3  1.0uF  [0402]
C4  4.7uF  [0402]
C7  10uF  [0402]
C8  10uF  [0402]
C12  10uF  [0603]
C13  10uF  [0603]
C101  27pF  [0402]
C102  10uF  [0402]
C103  10uF  [0402]
C104  DNS(0402)  [0402]
C105  DNS(0402)  [0402]
C106  DNS  [0805]
C107  DNS  [0805]
C108  DNS  [0805]
C109  DNS  [0805]
J22  HEADER-3  [HDR1X3]
J23  DNS  [HDR1X3]
JP5  DNS(HDR1X2)  [HDR1X2]
JP28  JUMPER-2  [HDR1X2]
JP29  DNS(HDR1X2)  [HDR1X2]
L1  2.2uH  [L_DFE252012F]
L16  2.2uH  [L_DFE252012F]
R6  1ohm  [0402]
R8  10K  [0402]
R15  100K  [0402]
R150  DNS  [0402]
R154  0ohm  [0805]
R155  DNS  [0402]
R156  DNS  [0402]
R157  0ohm  [0402]
R158  150K  [0402]
R159  300K  [0402]
R160  100K  [0402]
R161  0ohm  [0402]
R162  DNS  [0402]
R163  DNS  [0402]
R165  0ohm  [0402]
R166  DNS  [0402]
R172  4.7K  [0402]
R177  0ohm  [0402]
S1  SWI-SM-PTS645  [SWI-SM-PTS645]
SB1  Open  [SB]
SB4  Open  [SB]
SB6  Open  [SB]
SB9  Short  [SB]
SB15  Open  [SB]
SB16  Short  [SB]
TP3  DNS  [TESTPIN]
TP19  DNS  [TESTPIN]
TP25  TP-BLK  [TESTPIN]
TP28  DNS  [TESTPIN]
TP29  DNS  [TESTPIN]
TP30  TP-WHT  [TESTPIN]
U23  ATM5305-2NC8QK  [QFN-40-5X5-0.4MM]
U27  AP3401KTTR-G1  [SOT23-6]
U28  74LVC1G3157  [SOT-363]
Y1  32K XTAL  [XTAL-SMD2-2.0X1.2MM]
Y2  32M XTAL  [XTAL-1612]
sheet 04. GPIO Mapping
C56  0.1uF  [0402]
C59  0.1uF  [0402]
C60  0.1uF  [0402]
C72  0.1uF  [0402]
C90  0.1uF  [0402]
JP8  JUMPER-2  [HDR1X2]
JP11  JUMPER-2  [HDR1X2]
JP27  JUMPER-2  [HDR1X2]
R72  DNS  [0402]
R74  1M  [0402]
R79  DNS  [0402]
R98  1M  [0402]
R99  1M  [0402]
R152  10K  [0402]
R164  10K  [0402]
U7  NX3DV2567  [XQFN16]
U9  NX3DV2567  [XQFN16]
U11  NX3DV2567  [XQFN16]
U16  NX3DV2567  [XQFN16]
U26  NX3DV2567  [XQFN16]
sheet 05. RF (RFIO/Switch/Antenna)
ANT1  PIFA_2400MHz  [PIFA_2400MHZ_TRIMMED_2.8MM]
ANT2  PIFA_2400MHz  [PIFA_2400MHZ_TRIMMED_3.8MM]
C5  DNS(0402)  [0402]
C6  DNS(0402)  [0402]
C9  1.0pF  [0402]
C20  1.0pF  [0402]
C21  1.5pF  [0402]
C65  27pF  [0402]
C84  27pF  [0402]
C85  1.0pF  [0402]
C86  DNS  [0402]
C87  27pF  [0402]
C88  DNS(0402)  [0402]
C89  DNS(0402)  [0402]
J4  SMA_SL  [SMA-RA]
L11  3nH  [0402]
L12  2.7nH  [0402]
R1  0ohm  [0402]
R2  0ohm  [0402]
R96  DNS  [0402]
R129  0ohm  [0402]
R131  0ohm  [0402]
R149  DNS  [0402]
U1  XMSSJR8G2PA-246  [QFN6_1L1_0W7_0H6_0P4]
sheet 06. Buttons, LEDs, I/O
C35  DNS(0402)  [0402]
C36  DNS(0402)  [0402]
C37  DNS(0402)  [0402]
C38  DNS(0402)  [0402]
D10  150505M173300  [LED_WE_150141M173100_RGB]
J5  HEADER 5X2  [CON-SAMTEC-FTSH-10]
J12  HEADER 30X2  [HDR30X2]
Q1  MMBT3904/SOT  [TRA-SOT23]
Q2  MMBT3904/SOT  [TRA-SOT23]
Q3  MMBT3904/SOT  [TRA-SOT23]
R19  330  [0402]
R26  560  [0402]
R27  1K  [0402]
R28  300  [0402]
R29  1M  [0402]
R30  1K  [0402]
R31  1M  [0402]
R133  100K  [0402]
R134  100K  [0402]
R135  0ohm  [0402]
R136  0ohm  [0402]
R137  0ohm  [0402]
R138  0ohm  [0402]
R139  0ohm  [0402]
R140  0ohm  [0402]
R147  1K  [0402]
R148  100K  [0402]
R151  0ohm  [0402]
S2  SWI-SM-PTS645  [SWI-SM-PTS645]
S3  SWI-SM-PTS645  [SWI-SM-PTS645]
sheet 07. FTDI and USB
C33  4.7uF  [0402]
C39  4.7uF  [0402]
C40  0.1uF  [0402]
C45  0.1uF  [0402]
C46  4.7uF  [0402]
C91  0.1uF  [0402]
C92  3.3uF  [0603]
C93  0.1uF  [0402]
C94  4.7uF  [0402]
C95  0.1uF  [0402]
C96  3.3uF  [0603]
C97  0.1uF  [0402]
C99  27pF  [0402]
C100  27pF  [0402]
DS4  GREEN LED  [LED-0603]
J15  USB-C-2171790001  [MOLEX-2171790001]
L14  15uH  [0402]
L15  15uH  [0402]
R32  1K  [0402]
R33  470  [0402]
R35  12K  [0402]
R36  10K  [0402]
R37  10K  [0402]
R45  10K  [0402]
R46  33  [0402]
R47  33  [0402]
R118  0ohm  [0402]
R123  4.7K  [0402]
R142  5.1K  [0402]
R143  5.1K  [0402]
R145  10K  [0402]
R146  2K  [0402]
R153  DNS  [0402]
R167  4.7K  [0402]
R168  4.7K  [0402]
R169  4.7K  [0402]
R176  4.7K  [0402]
SB2  Short  [SB0201]
SB3  Short  [SB0201]
SB5  Short  [SB0201]
SB7  Short  [SB0201]
SB8  Short  [SB0201]
SB12  Short  [SB0201]
SB13  Short  [SB0201]
SB14  Short  [SB0201]
TP31  TP  [TESTPAD50]
TP32  TP  [TESTPAD50]
TP33  TP  [TESTPAD50]
U5  NSP4201MR6  [TSOP-6]
U6  FT4232HQ  [QFN-64-9X9MM-0.5]
U13  93LC56BT  [SOT23-6]
U22  74LVC1G08GV,125  [SOT23-5]
Y3  12M XTAL  [CRY-SMD4-3.2X2.5MM]
sheet 08. Level Shifters
C43  0.1uF  [0402]
C44  0.1uF  [0402]
C58  0.1uF  [0402]
C68  0.1uF  [0402]
C70  0.1uF  [0402]
C71  0.1uF  [0402]
R170  4.7K  [0402]
R171  4.7K  [0402]
R173  0ohm  [0402]
R174  0ohm  [0402]
R175  0ohm  [0402]
U8  NL3V4T244MU  [QFN-12-1.7X2]
U10  NL3V4T244MU  [QFN-12-1.7X2]
U12  NTB0104  [QFN-12-1.7X2]
sheet 09. Power
C47  DNS(0402)  [0402]
C48  1.0uF  [0402]
C49  1.0uF  [0402]
C50  1000pF  [0402]
C51  1.0uF  [0402]
C52  1.0uF  [0402]
C53  1000pF  [0402]
C54  1.0uF  [0402]
C55  1.0uF  [0402]
C61  0.01uF  [0402]
FD1  TEST POINT  [FID-G]
FD2  TEST POINT  [FID-G]
FD3  TEST POINT  [FID-G]
FD4  TEST POINT  [FID-G]
MT1  TEST POINT  [HOLE-250R125]
MT2  TEST POINT  [HOLE-250R125]
MT3  TEST POINT  [HOLE-250R125]
MT4  TEST POINT  [HOLE-250R125]
R53  0ohm  [0402]
R54  DNS  [0402]
R57  0ohm  [0402]
R58  27K  [0402]
R59  10K  [0402]
R60  0ohm  [0402]
R61  18.2K  [0402]
R62  20.5K  [0402]
TP21  DNS  [TESTPIN]
VR1  MIC5255-3.3YD5  [SOT23-5]
VR2  AP2127K-ADJTRG1  [SOT23-5]
VR3  AP2127K-ADJTRG1  [SOT23-5]
sheet 10. VDDIO-VCCIO Tracking
C74  1.0uF  [0402]
C75  0.1uF  [0402]
Q5  BSS84PW  [SOT-323]
R108  100K  [0402]
R109  120k  [0402]
R110  50  [0402]
R111  DNS  [0402]
R112  0ohm  [0402]
R113  0ohm  [0402]
SB10  Open  [SB]
U17  MCP6001  [SC70]
U18  TMUX1237  [SC70-6]
U19  MCP6001  [SC70]
U20  MCP6001  [SC70]
U21  MCP6001  [SC70]

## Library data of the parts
BT1 = BAT
C1 C7 C8 C102 C103 = SMALL_CAP: Manufacture_Name: MURATA; Manufacture_Part_Number: GRM155R60J106ME15D; Part Number: 01-2000011; Price: 0.00378; Datasheet: https://www.digikey.com/product-detail/en/murata-electronics-north-america/GRM155R60J106ME15D/490-13238-1-ND/5877446
C2 C3 C48 C49 C51 C52 C54 C55 C74 = SMALL_CAP: Manufacture_Name: MURATA; Manufacture_Part_Number: GRT155R61E105ME01D; Part Number: 01-2000007; Price: 0.003; Datasheet: https://www.digikey.com/product-detail/en/murata-electronics-north-america/GRT155R61E105ME01D/490-12264-1-ND/5416965
C4 = SMALL_CAP: Manufacture_Name: MURATA; Manufacture_Part_Number: GRM155R60J475ME47D; Part Number: 01-2000014; Price: 0.003; Datasheet: https://www.digikey.com/en/products/detail/murata-electronics/GRM155R60J475ME47D/3694656?s=N4IgTCBcDaIOICUCyBGArGhA2ADAKQBYB2NJAUWIBEQBdAXyA
C12 C13 = SMALL_CAP: Manufacture_Name: MURATA; Manufacture_Part_Number: GRM185R60J106ME15J; Part Number: 01-3000002; Price: 0.0038; Datasheet: https://www.digikey.com/en/products/detail/murata-electronics/GRM185R60J106ME15J/7363093
C84 C86 C87 C99-C101 = SMALL_CAP: Manufacture_Name: JOHANSON; Manufacture_Part_Number: QSCF500Q270J1GV001T; Datasheet: https://www.digikey.com/en/products/detail/johanson-technology-inc/qscf500q270j1gv001t/1561562
C5 C6 C35-C38 C47 C88 C89 C104 C105 = SMALL_CAP: Part Number: 01-2000016
C106-C109 = SMALL_CAP: Manufacture_Name: SAMSUNG; Manufacture_Part_Number: CL31A476MQHNNNE; Part Number: 01-4000005; Price: 0.03
J22 J23 = HEADER_3: Manufacture_Name: AMPHENOL ICC (FCI); Manufacture_Part_Number: 68000-103HLF; Part Number: 08-0000003; Datasheet: https://www.digikey.tw/en/products/detail/amphenol-cs-fci/68000-103HLF/2023309?s=N4IgTCBcDaIGwA4AMKC0BGJBmAEgGQDEQBdAXyA
JP5 JP29 = JUMPER-2: Part Number: 08-0000019
JP8 JP11 JP27 JP28 = JUMPER-2: Manufacture_Name: AMPHENOL ICC (FCI); Manufacture_Part_Number: 68000-102HLF; Part Number: 08-0000002; Price: 0.0066; Datasheet: https://www.digikey.com/products/en?keywords=68000-102HLF
L1 L16 = INDUCTOR: Manufacture_Name: MURATA; Manufacture_Part_Number: LQM2MPN2R2NG0L; Price: 0.025; Datasheet: https://www.digikey.com/en/products/detail/murata-electronics/LQM2MPN3R3NG0L/4359169?s=N4IgTCBcDaIDoBcAEAZAigWTBgCgOwGYAlAgOQHEAGFEAXQF8g
R6 = SMALL_R1: Manufacture_Name: YAGEO; Manufacture_Part_Number: RC0402FR-071RL; Part Description: RES 1 OHM 1% 1/16W 0402; Part Number: 03-2000032; Price: 0.0002; Datasheet: https://www.digikey.com/product-detail/en/yageo/RC0402FR-071RL/311-1.00LRCT-ND/729461
R8 R45 R59 R152 R164 = SMALL_R1: Manufacture_Name: WALSIN; Manufacture_Part_Number: WR04X1002FTL; Part Description: RES 10K OHM 1% 1/16W 0402; Part Number: 03-2000022; Price: 0.0002; Datasheet: https://www.digikey.com/en/products/detail/walsin-technology-corporation/WR04X1002FTL/13241339?s=N4IgTCBcDaIOoCUAMAWAGgRiUsAxAKgDIgC6AvkA
R15 R108 R133 R134 R148 R160 = SMALL_R1: Manufacture_Name: YAGEO; Manufacture_Part_Number: RC0402JR-07100KL; Part Number: 03-2000020; Price: 0.0002; Datasheet: https://www.digikey.com/en/products/detail/yageo/RC0402JR-07100KL/726416
R54 R72 R79 R96 R111 R149 R150 R153 R155 R156 R162 R163 R166 = SMALL_R1: Part Number: 03-2000042
R154 = SMALL_R1: Manufacture_Name: WALSIN; Manufacture_Part_Number: WR08X000 PTL; Part Number: 03-4000011; Price: 0.0004
R1 R2 R53 R57 R60 R112 R113 R118 R129 R131 R135-R140 R151 R157 R161 R165 R173-R175 R177 = SMALL_R1: Manufacture_Name: PANASONIC; Manufacture_Part_Number: ERJ-2GE0R00X; Part Number: 03-2000018; Price: 0.0002; Datasheet: https://www.digikey.com/en/products/detail/panasonic-electronic-components/erj-2ge0r00x/146727
R158 R159 = SMALL_R1: Price: 0.0002; Datasheet: https://www.digikey.com/en/products/detail/yageo/RC0402JR-07100KL/726416
R123 R167-R172 R176 = SMALL_R1: MF: WALSIN; Manufacture_Name: WALSIN; Manufacture_Part_Number: WR04X4701FTL; Part Number: 03-2000038; Price: 0.0002
S1-S3 = SW-TACT-4P-5: Manufacture_Name: C&K; Manufacture_Part_Number: PTS645SK50SMTR92 LFS; Part Number: 07-0000027; Datasheet: https://www.digikey.com/product-detail/en/c-k/PTS645SK50SMTR92-LFS/CKN9087CT-ND/1146813
SB1 SB4 SB6 SB10 SB15 = SB: Part Number: 03-1000006
SB2 SB3 SB5 SB7-SB9 SB12-SB14 SB16 = SB: Part Number: 03-1000004
TP3 TP25 = TP_3: Manufacture_Name: KEYSTONE ELECTRONICS; Manufacture_Part_Number: 36-5011-ND; Part Number: 08-0000006; Datasheet: https://www.digikey.com/product-detail/en/keystone-electronics/5011/36-5011-ND/255333
TP19 TP21 TP28-TP30 = TP_3: Manufacture_Name: KEYSTONE ELECTRONICS; Manufacture_Part_Number: 36-5012-ND; Part Number: 08-0000007; Datasheet: https://www.digikey.com/product-detail/en/keystone-electronics/5012/36-5012-ND/255334
U23 = Cairo_3
U27 = MIC5206ADJ_SO_0: Manufacture_Name: DIODES; Datasheet: https://www.digikey.com/en/products/detail/diodes-incorporated/AP3401KTTR-G1/6186982
U28 = 74LVC1G3157: Manufacture_Name: DIODES; Manufacture_Part_Number: 74LVC1G3157DW-7; Part Description: IC SWITCH SPDT X 1 10OHM SOT363; Part Number: 05-0000043; Datasheet: https://www.digikey.tw/zh/products/detail/diodes-incorporated/74LVC1G3157DW-7/6003946
Y1 = XTAL: Manufacture_Name: SEIKO; Manufacture_Part_Number: SC20S-7PF20PPM; Part Number: 06-0000018; Price: 0.065; Datasheet: https://www.digikey.com/short/797qhnc0
Y2 = XTAL-OSC-4P_0: Manufacture_Name: Hosonic; Manufacture_Part_Number: ETSB32E00000ME; Part Description: CRYSTAL 32MHZ +/- 8ppm,CL=9PF,ESR=60ohm,1.6mmx1.2mm,Hosonic; Part Number: 06-0000082; Price: 0.083; Datasheet: https://drive.google.com/file/d/1UCY43J5qyNmRNjoWmIyRl-3G5bXY6Cxz/view?usp=drive_link
C56 C59 C60 C72 C90 = SMALL_CAP: Manufacture_Name: TAIYO-YUDEN; Manufacture_Part_Number: TMK105BJ104KV-F; Part Number: 01-2000003; Price: 0.0013; Datasheet: https://www.digikey.com/en/products/detail/taiyo-yuden/TMK105BJ104KV-F/1004044
R29 R31 R74 R98 R99 = SMALL_R1: Manufacture_Name: YAGEO; Manufacture_Part_Number: RC0402JR-071ML; Part Number: 03-2000030; Price: 0.0002; Datasheet: https://www.digikey.com/product-detail/en/yageo/RC0402JR-071ML/311-1.0MJRCT-ND/729356
U7 U9 U11 U16 U26 = NX3DV2567: Manufacture_Name: NXP; Manufacture_Part_Number: NX3DV2567GU115; Part Description: NXP - NX3DV2567GU,115 - Analogue Switch, 4 Channels, 4PDT, 0.85 ohm, 1.4V to 4.3V, XQFN, 16 Pins; Part Number: 05-0000007; Datasheet: https://www.mouser.com/ProductDetail/NXP-Semiconductors/NX3DV2567GU115?qs=67TfscD5Pafw%252BgjlE0rl%2Fg%3D%3D
ANT1 ANT2 = PIFA_2400MHz: Manufacture_Name: ATMOSIC; Part Number: 09-0000013
C9 C20 C85 = SMALL_CAP: Manufacture_Name: JOHANSON; Manufacture_Part_Number: 500R07S1R0BV4T; Part Number: 01-2000006; Price: 0.001; Datasheet: https://www.digikey.com/en/products/detail/johanson-technology-inc/500R07S1R0BV4T/1561521?s=N4IgTCBcDaIKwAYECUEHYDKBGVAhAagCwAqIAugL5A
C21 = SMALL_CAP: Manufacture_Name: JOHANSON; Manufacture_Part_Number: QSCF500Q1R5B1GV001T; Part Description: CAP CER 1.5PF  ±0.1pF 50V C0G/NP0 0402; Part Number: 01-2000035; Price: 0.001; Datasheet: https://www.digikey.com/en/products/detail/johanson-technology-inc/QSCF500Q1R5B1GV001T/1561525?s=N4IgTCBcDaIDoBcAEBWADGgSmg7AZQEZMUAhANQBYAVEAXQF8g
C65 = SMALL_CAP: Manufacture_Name: WALSIN; Manufacture_Part_Number: 0402N270J500CT; Part Number: 01-2000024; Price: 0.001
J4 = SMA_SL: Manufacture_Name: CINCH CONNECTIVITY SOLUTIONS JOHNSON; Manufacture_Part_Number: 142-0701-801; Part Number: 08-0000005; Price: 1.03; Vendor: CINCH CONNECTIVITY SOLUTIONS JOHNSON; Datasheet: https://www.digikey.com/product-detail/en/cinch-connectivity-solutions-johnson/142-0701-801/J502-ND/35280
L11 = INDUCTOR: Manufacture_Name: TDK; Manufacture_Part_Number: MHQ1005P3N0BT000; Part Description: FIXED IND 3.0NH ±0.1nH 900MA 80 MOHM SMD; Part Number: 02-2000021; Price: 0.0035; Datasheet: https://www.digikey.com/en/products/detail/tdk-corporation/MHQ1005P3N0BT000/4742526?s=N4IgTCBcDaILIAkCKBGADGgrABQMwDk0AhAFQzRAF0BfIA
L12 = INDUCTOR: Manufacture_Name: TDK; Manufacture_Part_Number: MHQ1005P2N7BT000; Part Description: FIXED IND 2.7NH ±0.1nH 1A 70 MOHM SMD; Part Number: 02-2000002; Price: 0.0035; Datasheet: https://www.digikey.com/en/products/detail/tdk-corporation/mhq1005p2n7bt000/4742525
U1 = XMSSJR6G0BA-093: Manufacture_Name: MURATA; Part Description: 0.01-10.6GHz SPDT, QFN-6; Part Number: 06-0000087; Datasheet: https://www.murata.com/-/media/webrenewal/products/rfswitch/discreteswic/xm/xmssjr8g2pa-246.ashx?la=en&cvid=20221122060508000000
D10 = RGB_LED_1: Manufacture_Name: WURTH ELEKTRONIK; Datasheet: https://www.digikey.com/en/products/detail/w%C3%BCrth-elektronik/150505m173300/8557165
J5 = HEADER_5X2: Manufacture_Name: Samtec Inc.; Manufacture_Part_Number: FTSH-105-01-F-DV-K-TR; Part Number: 07-0000006
J12 = HEADER_30X2: Manufacture_Name: AMPHENOL ICC (FCI); Manufacture_Part_Number: 67996-160HLF; Datasheet: https://www.digikey.com/en/products/detail/amphenol-icc-fci/67996-160hlf/4273078
Q1-Q3 = MMBT3904_SOT: Manufacture_Name: NEXPERIA; Manufacture_Part_Number: PMBT3904-215; Part Number: 06-0000022; Datasheet: https://www.digikey.com/en/products/detail/nexperia-usa-inc/PMBT3904-215/763515
R19 = SMALL_R1: Price: 0.0002; Datasheet: https://www.digikey.com/en/products/detail/yageo/rc0402jr-07330rl/726465
R26 = SMALL_R1: Manufacture_Name: YAGEO; Manufacture_Part_Number: RC0402JR-07560RL; Part Number: 03-2000015; Price: 0.0002; Datasheet: https://www.digikey.com/en/products/detail/yageo/RC0402JR-07560RL/726492?s=N4IgTCBcDaIEoGEAMAWJYBScC0SDsArAGxJwAyIAugL5A
R27 R30 R147 = SMALL_R1: Manufacture_Name: WALSIN; Manufacture_Part_Number: WR04X1001FTL; Part Description: RES 1K OHM 1% 0402; Part Number: 03-2000028; Price: 0.0002; Datasheet: https://www.digikey.com/en/products/detail/walsin-technology-corporation/WR04X1001FTL/13240628?s=N4IgTCBcDaIOoCUAMAWAGgRiUjAxAKgDIgC6AvkA
R28 = SMALL_R1: Price: 0.0002; Datasheet: https://www.digikey.com/en/products/detail/yageo/RC0402JR-07300RL/726461?s=N4IgTCBcDaIEoGEAMAWJYBScC0SDsAzEknADIgC6AvkA
C33 C39 C46 C94 = SMALL_CAP: MF: Murata Electronics; Manufacture_Name: MURATA; Manufacture_Part_Number: GRM155R60J475ME47D; Part Number: 01-2000014; Price: 0.003; Datasheet: https://www.digikey.com/en/products/detail/murata-electronics/GRM155R60J475ME47D/3694656?s=N4IgTCBcDaIOICUCyBGArGhA2ADAKQBYB2NJAUWIBEQBdAXyA
C40 C45 C91 C93 C95 C97 = SMALL_CAP: MF: Murata Electronics; Manufacture_Name: MURATA; Manufacture_Part_Number: GMD155R71C104KA1D; Part Number: 01-2000002; Price: 0.0013
C92 = SMALL_CAP: Manufacture_Name: TDK; Manufacture_Part_Number: C1608JB1C335K080AC; Part Description: CAP CER 3.3UF 16V JB 0603; Part Number: 01-3000004; Price: 0.0104
C96 = SMALL_CAP: MF: Murata Electronics; Manufacture_Name: TDK; Manufacture_Part_Number: C1608JB1C335K080AC; Part Description: CAP CER 3.3UF 16V JB 0603; Part Number: 01-3000004; Price: 0.0104
DS4 = LED: Manufacture_Name: WURTH ELEKTRONIK; Manufacture_Part_Number: 150060GS75000; Part Number: 06-0000015; Price: 0.0043; Datasheet: https://www.digikey.com/en/products/detail/w%C3%BCrth-elektronik/150060GS75000/4489898?s=N4IgTCBcDaIIwFYAMSBsSDiBlA7MlIAugL5A
J15 = 2171790001_1: Manufacture_Name: MOLEX; Manufacture_Part_Number: 2171790001; Part Description: (USB) Shielded I/O Receptacle, Type C, 16 Circuits, Gold (Au) Plating; Part Number: 08-0000047
L14 L15 = INDUCTOR: MF: Murata Electronics; Manufacture_Name: MURATA; Manufacture_Part_Number: BLM15KD300SN1D; Part Number: 02-2000008; Price: 0.0034
R32 = SMALL_R1: MF: WALSIN; Manufacture_Name: WALSIN; Manufacture_Part_Number: WR04X1001FTL; Part Description: RES 1K OHM 1% 0402; Part Number: 03-2000028; Price: 0.0002; Datasheet: https://www.digikey.com/en/products/detail/walsin-technology-corporation/WR04X1001FTL/13240628?s=N4IgTCBcDaIOoCUAMAWAGgRiUjAxAKgDIgC6AvkA
R33 = SMALL_R1: MF: WALSIN; Manufacture_Name: YAGEO; Manufacture_Part_Number: RC0402JR-07470RL; Part Number: 03-2000012; Price: 0.0002; Datasheet: https://www.digikey.com/en/products/detail/yageo/RC0402JR-07470RL/726482?s=N4IgTCBcDaIEoGEAMAWJYBScC0SDsKeScAMiALoC%2BQA
R35 = SMALL_R1: MF: WALSIN; Manufacture_Name: WALSIN; Manufacture_Part_Number: WR04X1202FTL; Part Number: 03-2000023; Price: 0.0002
R36 R37 R145 = SMALL_R1: MF: WALSIN; Manufacture_Name: WALSIN; Manufacture_Part_Number: WR04X1002FTL; Part Description: RES 10K OHM 1% 1/16W 0402; Part Number: 03-2000022; Price: 0.0002; Datasheet: https://www.digikey.com/en/products/detail/walsin-technology-corporation/WR04X1002FTL/13241339?s=N4IgTCBcDaIOoCUAMAWAGgRiUsAxAKgDIgC6AvkA
R46 R47 = SMALL_R1: Manufacture_Name: YAGEO; Manufacture_Part_Number: RC0402JR-0733RL; Part Number: 03-2000003; Price: 0.0002; Datasheet: https://www.digikey.com/en/products/detail/yageo/RC0402JR-0733RL/726467?s=N4IgTCBcDaIDoBcAEAlAwgBgCwbAKRQFoMB2AZjJQBkQBdAXyA
R142 R143 = SMALL_R1: Manufacture_Name: YAGEO; Manufacture_Part_Number: RT0402FRE075K1L; Part Description: RES SMD 5.1K OHM 1% 1/16W; Part Number: 03-2000062; Price: 0.0002
R146 = SMALL_R1: MF: WALSIN; Manufacture_Name: WALSIN; Manufacture_Part_Number: WR04X2001FTL; Part Number: 03-2000034; Price: 0.0002
TP31-TP33 = TP_0: Part Number: 09-0000005
U5 = NSP4201MR6_0: Manufacture_Name: onsemi; Manufacture_Part_Number: NSP4201MR6T1G; Part Description: TVS DIODE 5VWM 12VC 6TSOP; Part Number: 05-0000023; Datasheet: https://www.digikey.com/product-detail/en/on-semiconductor/NSP4201MR6T1G/NSP4201MR6T1GOSCT-ND/7556459
U6 = FT4232HQ-REEL_3: MF: FDTI; Manufacture_Name: FDTI; Part Number: 05-0000008; Price: 5.5
U13 = 93LC56BT-I_OT: MF: Microchip Technology; Manufacture_Name: MICROCHIP; Manufacture_Part_Number: 93LC56BT-I/OT; Part Number: 05-0000010; Price: 0.21
U22 = 54AS00_1: Manufacture_Name: NEXPERIA; Part Description: AND Gate IC 1 Channel SC-74A, 1.65~6.5V; Part Number: 05-0000034; Datasheet: https://www.digikey.com/en/products/detail/nexperia-usa-inc/74lvc1g08gv-125/1231422
Y3 = XTAL-OSC-4P_0: MF: Kyocera; Manufacture_Name: Kyocera; Manufacture_Part_Number: CX3225SB12000H0FLJCC; Part Description: CRYSTAL 12.0000MHZ 12PF SMD; Part Number: 06-0000031; Price: 0.35
C43 C44 C58 C68 C70 C71 = SMALL_CAP: Manufacture_Name: MURATA; Manufacture_Part_Number: GMD155R71C104KA1D; Part Number: 01-2000002; Price: 0.0013
U8 U10 = NTB0104_1: Manufacture_Name: ON Semiconductor; Manufacture_Part_Number: NL3V4T244MU2TAG-Q; Part Description: IC XLTR VL UNIDIR 12-UQFN LOW ACTIVE; Part Number: 05-0000041; Datasheet: https://www.digikey.tw/zh/products/detail/onsemi/NL3V4T244MU2TAG/25586100
U12 = NTB0104: Manufacture_Name: NXP; Manufacture_Part_Number: NTB0104GU12,115; Datasheet: https://www.digikey.com/en/products/detail/nxp-usa-inc/NTB0104GU12-115/2523425
C50 C53 = SMALL_CAP: Manufacture_Name: MURATA; Manufacture_Part_Number: GRM155R72A102KA01D; Part Description: CAP CER 1000PF 100V ±10% X7R 0402; Part Number: 01-2000026; Price: 0.001; Datasheet: https://www.digikey.com/en/products/detail/murata-electronics/GRM155R72A102KA01D/2610953?s=N4IgTCBcDaIOICUCyBGArGhB2MBBFADGANK4EoAiIAugL5A
C61 = SMALL_CAP: Manufacture_Name: TDK; Manufacture_Part_Number: CGA2B3X7R1H103K050BB; Part Number: 01-2000001; Price: 0.0016; Datasheet: https://www.digikey.com/en/products/detail/tdk-corporation/CGA2B3X7R1H103K050BB/2672786
FD1-FD4 = TEST_POINT: Part Number: 09-0000007
MT1-MT4 = TEST_POINT: Part Number: 09-0000006
R58 = SMALL_R1: Manufacture_Name: YAGEO; Manufacture_Part_Number: RC0402FR-0727KL; Part Number: 03-2000033; Price: 0.0002; Datasheet: https://www.digikey.com/en/products/detail/yageo/RC0402FR-0727KL/726574
R61 = SMALL_R1: Manufacture_Name: YAGEO; Manufacture_Part_Number: RC0402FR-0718K2L; Part Description: RES 18.2K OHM 1% 0402; Part Number: 03-2000080; Price: 0.0002; Datasheet: https://www.digikey.com/en/products/detail/yageo/RC0402FR-0718K2L/2345132
R62 = SMALL_R1: Manufacture_Name: YAGEO; Manufacture_Part_Number: RC0402FR-0720K5L; Part Description: RES 20.5K OHM 1% 0402; Part Number: 03-2000081; Price: 0.0002; Datasheet: https://www.digikey.com/en/products/detail/yageo/RC0402FR-0720K5L/5280912
VR1 = VAR_REG: Manufacture_Name: MICREL; Part Description: IC REG LIN 3.3V 150MA TSOT23-5; Part Number: 06-0000037; Price: 0.48; Datasheet: https://www.digikey.com/en/products/detail/microchip-technology/MIC5255-3-3YD5-TR/1030949?s=N4IgTCBcDaILIEkDCBWMKUFoDMA6bAmgCIogC6AvkA
VR2 VR3 = VAR_REG: Manufacture_Name: DIODES; Part Description: IC REG LIN POS ADJ 300MA SOT23-5; Part Number: 06-0000032; Price: 0.094; Datasheet: https://www.digikey.com/en/products/detail/diodes-incorporated/AP2127K-ADJTRG1/4470788?s=N4IgTCBcDaIIIAUwEYwHYDSBaOARAUgCoBKA4siALoC%2BQA
C75 = SMALL_CAP: Manufacture_Name: TAIYO-YUDEN; Manufacture_Part_Number: TMK105BJ104KV-F; Part Number: 01-2000003; Price: 0.0013; Vendor: TAIYO-YUDEN; Datasheet: https://www.digikey.com/en/products/detail/taiyo-yuden/TMK105BJ104KV-F/1004044
Q5 = BSS84_SOT_0: Manufacture_Name: INFINEON; Manufacture_Part_Number: BSS84PWH6327XTSA1; Part Description: PMOS 60 V 150mA (Ta) 300mW (Ta) SOT323; Part Number: 06-0000057; Datasheet: https://www.digikey.com/en/products/detail/infineon-technologies/BSS84PWH6327XTSA1/5410126
R109 = SMALL_R1
R110 = SMALL_R1: Manufacture_Name: YAGEO; Manufacture_Part_Number: RC0402JR-0750RL; Part Description: RES 50 OHM 5% 1/16W 0402; Part Number: 03-2000072; Price: 0.0002; Datasheet: https://www.digikey.com/en/products/detail/yageo/RC0402JR-0750RL/5917787?s=N4IgTCBcDaIEoGEAMAWJYBScC0SDsArEnADIgC6AvkA
U17 U19-U21 = MCP6001: Manufacture_Name: Microchip Technology; Manufacture_Part_Number: MCP6001T-E/LT; Part Description: IC OPAMP GP 1 CIRCUIT SOT23-5; Part Number: 05-0000021; Datasheet: https://www.digikey.com/en/products/detail/microchip-technology/MCP6001T-E-LT/683192
U18 = TMUX1237: Manufacture_Name: Texas Instruments; Manufacture_Part_Number: TMUX1237DCKR; Part Description: IC SWITCH SPDT X 1 4.5OHM SC70-6; Part Number: 05-0000022; Datasheet: https://www.digikey.com/en/products/detail/texas-instruments/tmux1237dckr/12165109

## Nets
1.5V: J23.1 R60.2
3.0V: C37.2 C38.1 J22.1 R57.2 R140.1 U28.5(Vcc)
3.3V: C39.2 C40.1 C44.2 C45.1 C46.2 C58.2 C71.2 L14.1 L15.1 R19.1 R26.1 R28.1 R32.1 R36.1 R37.1 R53.2 R109.1 R145.1 U6.20(VCCIO) U6.31(VCCIO) U6.42(VCCIO) U6.50(VREGIN) U6.56(VCCIO) U8.11(VCCB) U10.1(VCCA) U12.11(VCCB) U13.6(VCC) U22.5(VCC)
GND: J15.13(SGND) J15.14(SGND) J15.15(SGND) J15.16(SGND) SB2.2 SB3.2 SB5.2 SB7.2 SB8.2 SB12.2 SB13.2 SB14.2
GND_SIGNAL: ANT1.2(GND) ANT1.3(GND1) ANT2.2(GND) ANT2.3(GND1) BT1.2(NEG) C1.2 C2.2 C3.2 C4.2 C5.2 C6.2 C7.2 C8.2 C9.2 C12.2 C13.2 C20.1 C21.1 C33.1 C35.1 C36.2 C37.1 C38.2 C39.1 C40.2 C43.1 C44.1 C45.2 C46.1 C48.1 C49.1 C51.1 C52.1 C54.1 C55.1 C56.2 C58.1 C59.2 C60.2 C61.1 C68.1 C70.1 C71.1 C72.2 C74.2 C75.2 C85.2 C88.2 C89.2 C90.2 C91.2 C92.1 C93.2 C94.1 C95.2 C96.1 C97.2 C99.2 C100.2 C102.2 C103.2 C104.1 C105.1 C106.2 C107.2 C108.2 C109.2 J4.2(GND1) J4.3(GND2) J5.3 J5.5 J12.59 J15.A1/B12(GND) J15.B1/A12(GND_2) MT2.1 MT4.1 Q1.2(E) Q2.2(E) Q3.2(E) R8.1 R15.1 R29.1 R35.2 R45.1 R59.2 R62.2 R72.1 R74.1 R79.1 R98.1 R99.1 R108.2 R111.2 R123.2 R133.1 R134.1 R135.2 R136.2 R137.2 R138.2 R139.2 R142.1 R143.1 R148.1 R156.1 R158.2 R167.2 R168.2 R169.2 R170.2 R171.2 R172.2 R173.2 R174.2 R176.2 S3.3 S3.4 SB2.1 SB3.1 SB5.1 SB6.2 SB7.1 SB8.1 SB12.1 SB13.1 SB14.1 TP3.1(TP) TP25.1(TP) U1.2(GND) U5.2(GND) U6.1(GND) U6.5(GND) U6.10(AGND) U6.11(GND) U6.13(TEST) U6.15(GND) U6.25(GND) U6.35(GND) U6.47(GND) U6.51(GND) U6.65(EPAD) U7.6(GND) U8.6(GND) U9.6(GND) U10.6(GND) U11.6(GND) U12.6(GND) U13.2(VSS) U16.6(GND) U17.2 U18.5(S6) U19.2 U20.2 U21.2 U22.3(GND) U23.41(EGND) U26.6(GND) U27.2(GND) U28.2(GND) VR1.2(GND) VR2.2(GND) VR3.2(GND) Y2.2(NC) Y2.4(NC) Y3.2(NC) Y3.4(NC)
VBAT1V: C7.1 C105.2 JP5.1 L1.1 R155.2 R166.1 R177.2 SB1.2 SB9.1 U23.31(VBAT1V)
VBAT3V: BT1.1(POS) C8.1 C104.2 C106.1 C107.1 C108.1 C109.1 JP28.2 R154.1 R157.2 R163.2 R165.2 SB4.2 SB15.2 U23.29(VBAT3V)
VCC_1P8_FTDI: C92.2 C93.1 C96.2 C97.1 U6.12(VCORE) U6.37(VCORE) U6.49(VREGOUT) U6.64(VCORE)
VCC_S: C35.2 C36.1 J12.60 R31.2 S2.3 S2.4 U16.1(1Y0)
VCCIO: C43.2 C56.1 C59.1 C60.1 C68.2 C70.2 C72.1 C90.1 J5.1 J12.58 JP8.1 JP11.1 JP27.1 R113.2 R175.1 SB10.2 U7.14(VCC) U8.1(VCCA) U9.14(VCC) U10.11(VCCB) U11.14(VCC) U12.1(VCCA) U16.14(VCC) U26.14(VCC)
VDDIO: C4.1 R112.1 R150.2 SB1.1 SB4.1 SB10.1 TP29.1(TP) U16.16(1Z) U23.28(VDDIO)
VDDPA: C101.1 C102.1 L16.2 R159.1 R162.1
Ant_Sw: R131.2 U26.9(3Y0)
Ant_VDD: R129.2 U26.13(4Y0)
BBOOT: U10.8(B3) U11.5(2Y0)
BUTTON_0: R29.2 S2.1 S2.2 U26.1(1Y0)
BUTTON_1: R31.1 S3.1 S3.2 U26.5(2Y0)
Disable_UART0: JP8.2 R79.2 R99.2 R164.2 U7.2(S) U9.2(S)
DM: R46.2 U6.7(DM)
DP: R47.2 U6.8(DP)
Ext_1.5V: J23.3 TP19.1(TP)
Ext_3.0V: J22.3 TP30.1(TP)
FT4232_RST: R32.2 U6.14(~{RESET#})
FTDI_BBOOT: R118.1 R153.1 U10.4(A3)
FTDI_PWD: R172.1 U6.24(ADBUS7) U28.6(S)
FTDI_SWD_Disable: R170.1 U6.22(ADBUS5) U12.8(B3)
FTDI_SWDCLK: U6.16(ADBUS0) U12.10(B1)
FTDI_SWDIO: R33.2 U6.18(ADBUS2) U12.9(B2)
FTDI_UART0_CTS: U6.41(CDBUS3) U8.9(B2)
FTDI_UART0_RTS: R176.1 U6.40(CDBUS2) U10.3(A2)
FTDI_UART0_RX: U6.39(CDBUS1) U8.10(B1)
FTDI_UART0_TX: U6.38(CDBUS0) U10.2(A1)
FTDI_UART1_RX: U6.27(BDBUS1) U8.8(B3)
FTDI_UART1_TX: R153.2 U6.26(BDBUS0) U22.2(B)
FTDI_UART_Disable: R171.1 U6.21(ADBUS4) U12.7(B4)
LED_0: R147.1 R148.2 U16.5(2Y0)
LED_1: R27.1 R133.2 U16.9(3Y0)
LED_2: R30.1 R134.2 U16.13(4Y0)
LED_Disable: JP27.2 R72.2 R98.2 U16.2(S) U26.2(S)
LIOn_Bat: JP28.1 R151.1 SB15.1 U23.32(MON_VSTORE)
P0: J5.4 J12.1 U11.8(3Z) U23.4(P0)
P1: J5.2 J12.2 U11.12(4Z) U23.5(P1)
P8: J12.9 U16.4(2Z) U23.6(P8)
P9: J12.10 U16.8(3Z) U23.7(P9)
P10: J12.11 U16.12(4Z) U23.8(P10)
P11: J12.12 U23.9(P11) U26.16(1Z)
P12: J12.13 U23.10(P12) U26.4(2Z)
P13: J12.14 R149.1 U23.11(P13) U26.8(3Z)
P14: J12.15 R96.1 U23.12(P14) U26.12(4Z)
P15: J12.16 U23.13(P15)
P16: J12.17 U23.14(P16)
P17: J12.18 U9.4(2Z) U23.15(P17)
P25: J5.8 J12.26 R15.2 U11.4(2Z) U23.17(P25)
P26: J12.27 U23.18(P26)
P27: J12.28 U7.12(4Z) U23.19(P27)
P28: J12.29 U7.8(3Z) U23.20(P28)
P29: J12.30 U7.4(2Z) U23.21(P29)
P30: J12.31 U9.8(3Z) U23.22(P30)
P37: J12.38 U23.33(P37/HARV)
P38: J12.39 U23.34(P38)
P39: J12.40 U23.35(P39)
P41: J12.42 U23.36(P41)
P45: J12.46 U23.39(P45)
P47: J12.48 U23.40(P47)
PWD: J5.9 J12.50 R8.2 S1.1 S1.2 U23.26(PWD) U28.4(A)
RFIO: L11.2 U23.2(RFIO)
SWD_Disable: R152.1 U12.4(A3)
SWDCLK: U11.9(3Y0) U12.2(A1)
SWDIO: U11.13(4Y0) U12.3(A2)
UART0_CTS: U9.9(3Y0) U10.9(B2)
UART0_RTS: U8.3(A2) U9.5(2Y0)
UART0_RX: U7.9(3Y0) U10.10(B1)
UART0_TX: U7.5(2Y0) U8.2(A1)
UART1_TX: U7.13(4Y0) U8.4(A3)
UART_Disable: R164.1 U12.5(A4)
USB_D+: J15.A6(DP1) J15.B6(DP2) R47.1 U5.3(IO2) U5.4(IO3)
USB_D-: J15.A7(DN1) J15.B7(DN2) R46.1 U5.1(IO1) U5.6(IO4)
USB_VBUS: C49.2 C52.2 C55.2 C75.1 DS4.2(ANODE) J15.A4/B9(VBUS) J15.B4/A9(VBUS_2) Q5.2(S) TP21.1(TP) U5.5(VP) U17.5 U18.2(VDD) U19.5 U20.5 U21.5 VR1.1(VIN) VR1.3(EN) VR2.1(VIN) VR2.3(EN) VR3.1(VIN) VR3.3(EN)
N16433775: SB6.1 U23.25(XTALI_32K) Y1.2
N16433919: U23.37(XTALI_32M) Y2.3(HOT)
N16438070: C12.1 C13.1 R6.1 U23.1(VBAT1V_A)
N16440684: C1.1 TP28.1(TP) U23.23(DVDD)
N16735640: JP5.2 R6.2 SB9.2
N16847204: R174.1 U10.12(~{OE})
N16949418: U23.24(XTALO_32K) Y1.1
N17095028: C47.2 C48.2 R53.1 R54.1 VR1.5(VOUT)
N17095050: C47.1 C61.2 R54.2 VR1.4(ADJ)
N17095279: C53.2 C54.2 R60.1 R61.1 VR3.5(VOUT)
N17095319: C53.1 R61.2 R62.1 VR3.4(ADJ)
N17095531: C50.2 C51.2 R57.1 R58.1 VR2.5(VOUT)
N17095557: C50.1 R58.2 R59.1 VR2.4(ADJ)
N17099553: JP11.2 R74.2 R152.2 U11.2(S)
N17101185: C20.2 C65.2 C86.1 L12.1
N17101189: C21.2 L11.1 L12.2
N17105834: DS4.1(CATHODE) R45.2
N17109714: R165.1 R166.2 S1.3 S1.4 U28.1(B1)
N17182443: R108.1 R109.2 U17.3
N17182456: U18.1(S2) U19.3 U20.1 U20.4
N17182464: U18.6(SEL) U19.1
N17182470: U17.1 U17.4 U18.3(S1) U19.4
N17182563: Q5.3(D) R111.1 R113.1 U21.3
N17182569: R112.2 U20.3
N17182581: Q5.1(G) U21.1
N17182601: R110.2 U18.4(D)
N17182603: C74.1 R110.1 U21.4
N17333588: L1.2 U23.30(SW)
N17354175: C85.1 R131.1 R149.2 U1.6(CTL)
N17354201: ANT2.1(FEED) C6.1 R2.2
N17354207: C5.1 C84.2 R2.1
N17354215: C84.1 U1.1(PORT2)
N17354302: C86.2 U1.5(C-PORT)
N17354317: C87.1 U1.3(PORT1)
N17354321: C9.1 R96.2 R129.1 U1.4(VDD)
N17354357: ANT1.1(FEED) C88.1 R1.2
N17354363: C87.2 C89.1 R1.1
N17355105: C65.1 J4.1(IO)
N17362888: J12.49 R135.1
N17362893: J12.51 R136.1
N17362902: J12.53 R137.1
N17362907: J12.55 R138.1
N17362912: J12.57 R139.1
N17379393: J15.B5(CC2) R142.2
N17379398: J15.A5(CC1) R143.2
N17383929: C33.2 C91.1 L14.2 U6.9(VPLL)
N17384041: C94.2 C95.1 L15.2 U6.4(VPHY)
N17384381: R35.1 U6.6(REF)
N17384498: R146.1 U13.1(DO)
N17384504: R36.2 R146.2 U6.61(EEDATA) U13.3(DI)
N17384506: R37.2 U6.62(EECLK) U13.4(CLK)
N17384508: R145.2 U6.63(EECS) U13.5(CS)
N17384576: C99.1 U6.2(OSCI) Y3.1(HOT)
N17384598: C100.1 U6.3(OSCO) Y3.3(HOT)
N17388389: R33.1 U6.17(ADBUS1)
N17396057: R173.1 U8.12(~{OE})
N17396121: R175.2 U12.12(OE)
N17402292: D10.2(BA) R28.2
N17402381: D10.1(BC) Q3.3(C)
N17402415: D10.4(BA) R19.2
N17402620: D10.5(GA) Q2.3(C)
N17402743: D10.6(BA) R26.2
N17404413: D10.3(RA) Q1.3(C)
N17437750: J22.2 R154.2
N17437756: J23.2 R155.1
N17446987: R156.2 R157.1 U23.27(MODE)
N17450009: C103.1 R160.1 R161.1 R163.1 U27.4(VIN)
N17450013: R161.2 U27.1(EN)
N17450071: R160.2 U27.5(PG)
N17450073: L16.1 U27.3(LX)
N17450095: C101.2 R158.1 R159.2 U27.6(FB)
N17450384: JP29.2 R150.1 R162.2 R177.1 SB16.2
N17453610: R123.1 U6.23(ADBUS6) U22.1(A)
N17453636: R118.2 U22.4(Y)
N17472236: U23.38(XTALO_32M) Y2.1(HOT)
N17473117: C2.1 JP29.1 SB16.1 U23.3(VDDPA)
N17490666: C3.1 U23.16(VDDIO)
N17528491: R167.1 TP31.1(TP) U6.57(DDBUS5)
N17528504: R168.1 TP32.1(TP) U6.58(DDBUS6)
N17528517: R169.1 TP33.1(TP) U6.59(DDBUS7)
N17555308: J12.56 R140.2
N17555309: Q1.1(B) R147.2
N17555310: Q3.1(B) R30.2
N17555311: Q2.1(B) R27.2
N17555312: J12.54 R151.2

Not connected (* = marked no-connect by the designer): FD1 1*; FD2 1*; FD3 1*; FD4 1*; J5 6* 7* 10*; J12 3* 4* 5* 6* 7* 8* 19* 20* 21* 22* 23* 24* 25* 32* 33* 34* 35* 36* 37* 41* 43* 44* 45* 47* 52*; J15 A8(SBU1)* B8(SBU2)*; MT1 1; MT3 1; U6 19(ADBUS3)* 28(BDBUS2)* 29(BDBUS3)* 30(BDBUS4)* 32(BDBUS5)* 33(BDBUS6)* 34(BDBUS7)* 36(~{SUSPEND#})* 43(CDBUS4)* 44(CDBUS5)* 45(CDBUS6)* 46(CDBUS7)* 48(DDBUS0)* 52(DDBUS1)* 53(DDBUS2)* 54(DDBUS3)* 55(DDBUS4)* 60(~{PWREN#})*; U7 1(1Y0)* 3(2Y1)* 7(3Y1)* 10(N_C_)* 11(4Y1)* 15(1Y1)* 16(1Z)*; U8 5(A4)* 7(B4)*; U9 1(1Y0)* 3(2Y1)* 7(3Y1)* 10(N_C_)* 11(4Y1)* 12(4Z)* 13(4Y0)* 15(1Y1)* 16(1Z)*; U10 5(A4)* 7(B4)*; U11 1(1Y0)* 3(2Y1)* 7(3Y1)* 10(N_C_)* 11(4Y1)* 15(1Y1)* 16(1Z)*; U16 3(2Y1)* 7(3Y1)* 10(N_C_)* 11(4Y1)* 15(1Y1)*; U26 3(2Y1)* 7(3Y1)* 10(N_C_)* 11(4Y1)* 15(1Y1)*; U28 3(B0)*

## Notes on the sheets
sheet 1
- ATM5305/5205 5x5 QFN EVALUATION BOARD
- Release Date
- Revision
- Design Eng.
- Design Notes
- 10/06/25
- -00
- AD
- Initial release
- 19/03/26
- -10
- AD
- Changed SMA Connector J4 from Molex to TE
  Swapped VCCA and VCCB on level shifter U12; Added UART_disable to U12
  Changed from 3.0V to VBAT3V for Power down switch S1
  Changed how FTDI_PWD signal interfaces with Cairo: using analog switch instead of level shifter
  Changed UART1_TX to P27 and UART0_RTS to P17
  Added options to disable level shifters through the OE pin
- 7/9/26
- -20
- JOE
- Add SB15 / JP28 as a selectable connection option between MON_VSTORE and VBAT3V.
- Add R177/0402/0ohm between VDDPA and VBAT1V.
- Add JP29/DNS(HDR1x2) and SB16 for VDDPA current measurement.
- Replace J4 from vertical-launch SMA to side-launch SMA connector.
- Add bulk capacitor placeholders at C106, C107, C108 and C109 for BT1. DNS(47µF/0805) by default.
- ATMOSIC TECHNOLOGIES INC
- Atmosic Technologies, Inc
- 2130 Gold Street, Suite 200
  San Jose, CA 95002
- Atmosic Technologies Proprietary and Confidential
sheet 2
- Page 1 - Revision notes
  Page 2 - Block diagram
  Page 3 - ATM5305, decoupling
  Page 4 - GPIO Mapping, Analog switches
  Page 5 - RF matching circuits
  Page 6 - LEDs, Buttons, I/O Interface Connector
  Page 7 - FTDI
  Page 8 - Level Shifters
  Page 9 - Power supplies and configurations
  Page 10 - VDDIO-VCCIO tracking circuit
- Block Diagram
- Ext Supply
  Conn
- SMA Conn
- USB-C
  Conn
- On-board LDOs
- Mode
- 3.0V
- 3.3V
- 1.5V
- Switches
- Buttons
  RGB LEDs
- EEPROM
- Analog
  Switches
- Printed
  Antenna 1
- FTDI
- Level
  Shifters
- 60-pin
  Connector
- SWD, BBOOT
  UART0
  UART1_TX/RX
- 12M XTAL
- ATM5305
- BLE Tx/Rx
  Match
- Antenna
  Switch
- VCCIO-VDDIO
- Tracking Ckt
- Printed
  Antenna 2
- GPIOs: P0 - P47
- Reset Button
- ATMOSIC TECHNOLOGIES INC
sheet 3
- MON_VSTORE connect to VBAT3V
- Ext 3.0V
- (LDO)
- (LDO)
- Ext 1.5V
- Ext VDDIO
- Ext DVDD
- Bulk capacitors 47uF/0805
  for CR2032 BAT(BT1)
- (0805)
- If R155 is installed, R156 should be installed,
  and R154 and R157 should be removed
- Mode
- R154
- R155
- R156
- R157
- R165
- R166
- R156 and R157 share one common PCB pad
  (only one can be installed at a time)
- Battery is installed by Atmosic only
  for customized stand-alone battery
  operated applications without USB.
  SB10 will be shorted to connect
  VCCIO-VDDIO
- Buck
- Yes
- No
- No
- Yes
- Yes
- No
- Boost
- No
- Yes
- Yes
- No
- No
- Yes
- Optional DC-DC 3V to 1.8V Converter
- For lower power consumption in Tx mode
  when transmitting at 8dBm or 10dBm,
  install R162 and R163 and remove R150
- ATM5305-2NC8QK
- For VBAT3V power supply, VDDPA connects to VBAT1V by default.
- Buck Mode: Install R165, Remove R166
  Boost Mode: Remove R165, Install R166
- PTS645 SMD
- Power down switch
- Benign boot
- ATMOSIC TECHNOLOGIES INC
- FTDI_PWD
- U28, Pin 4
- HIGH (3.3V)
- LOW (0V)
- =Pin 1 (VBAT3V/VBAT1V)
- =Pin 3 (Open)
- Atmosic Technologies Proprietary and Confidential
sheet 4
- CONNECT ATM5305 to LEDS/BUTTONS/RF switch
- ISOLATE ATM5305 SWD from FTDI
- CONNECT ATM5305 UARTs to FTDI
- Install to
  isolate LEDs,
  Buttons,
  RF Switch
- Install to
  isolate SWD
- Install to
  isolate UARTs
- Assert to isolate SWD
- Assert to isolate UARTs
- ATMOSIC TECHNOLOGIES INC
- Atmosic Technologies Proprietary and Confidential
sheet 5
- FT4232HQ
- USB ESD
- (Benign Boot
       /
     UART1_RX)
- USB-C USB2.0 Connector
- EEPROM
- 12MHz XTAL
- ATMOSIC TECHNOLOGIES INC
sheet 6
- FTDI --> ATM53xx
- ATM53xx --> FTDI
- ATM53xx <--> FTDI
- ATMOSIC TECHNOLOGIES INC
sheet 7
- USB_VBUS
- Supply for FTDI IO
- On-Board Voltage Regulators
- Supply for VBAT1V
- Supply for VBAT3V
- MOUNTING HOLES
- BOARD FIDUCIALS
- ATMOSIC TECHNOLOGIES INC
sheet 8
- VDDIO < 1.5V: VCCIO = 1.5V
  VDDIO >=1.5V: VCCIO = VDDIO
- Short this SB10 for Battery Operation
sheet 9
- LEDS
- PUSH BUTTONS
- 60-PIN CONNECTOR I/O INTERFACE
- PTS645 SMD
- PTS645 SMD
- J-Link 9-pin Cortex-M
- Samtec FTSH-105-01
- ATMOSIC TECHNOLOGIES INC
sheet 10
- Ext SMA
- BLE front-end match
- Note:
  For inductors, use MHQ series from TDK.
  For capacitors, use Johanson
- ATMOSIC TECHNOLOGIES INC
- Atmosic Technologies Proprietary and Confidential
